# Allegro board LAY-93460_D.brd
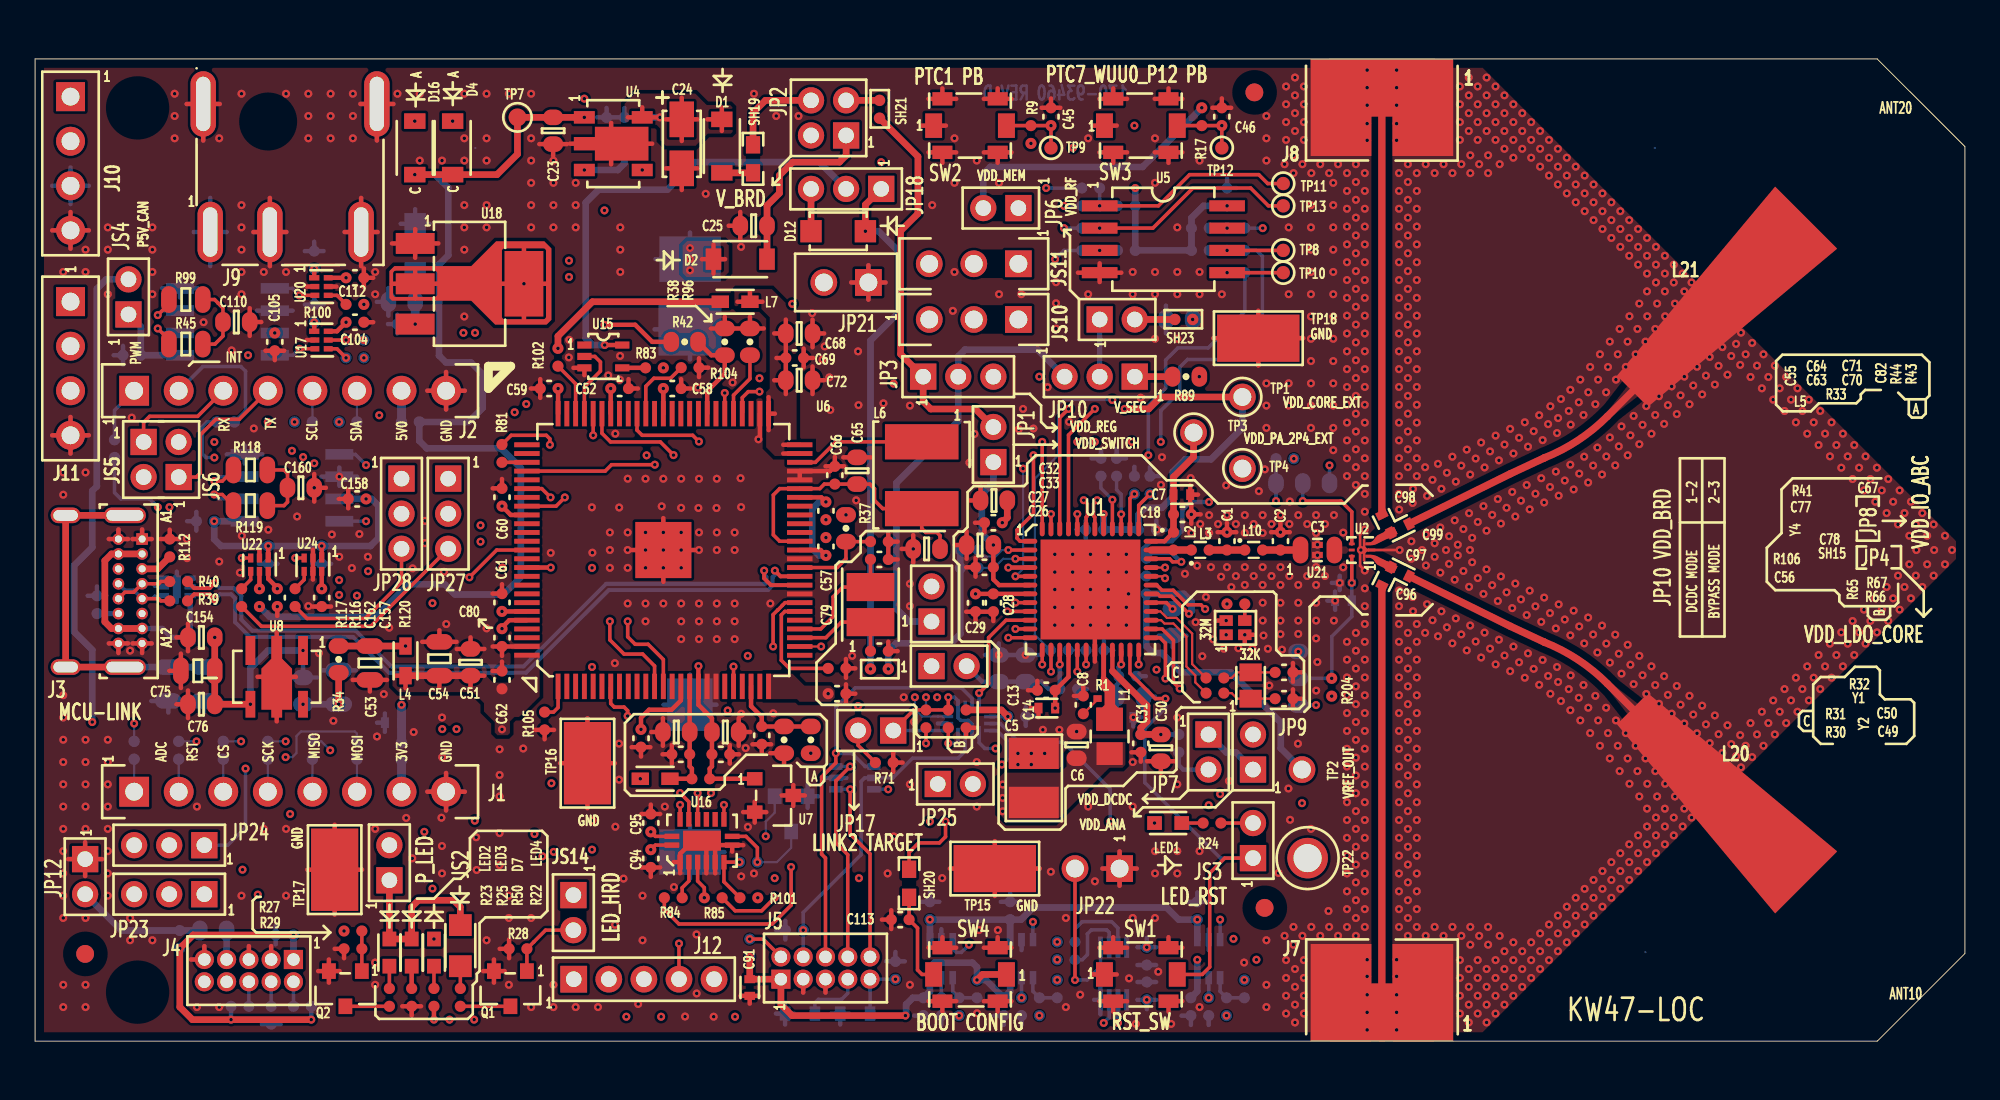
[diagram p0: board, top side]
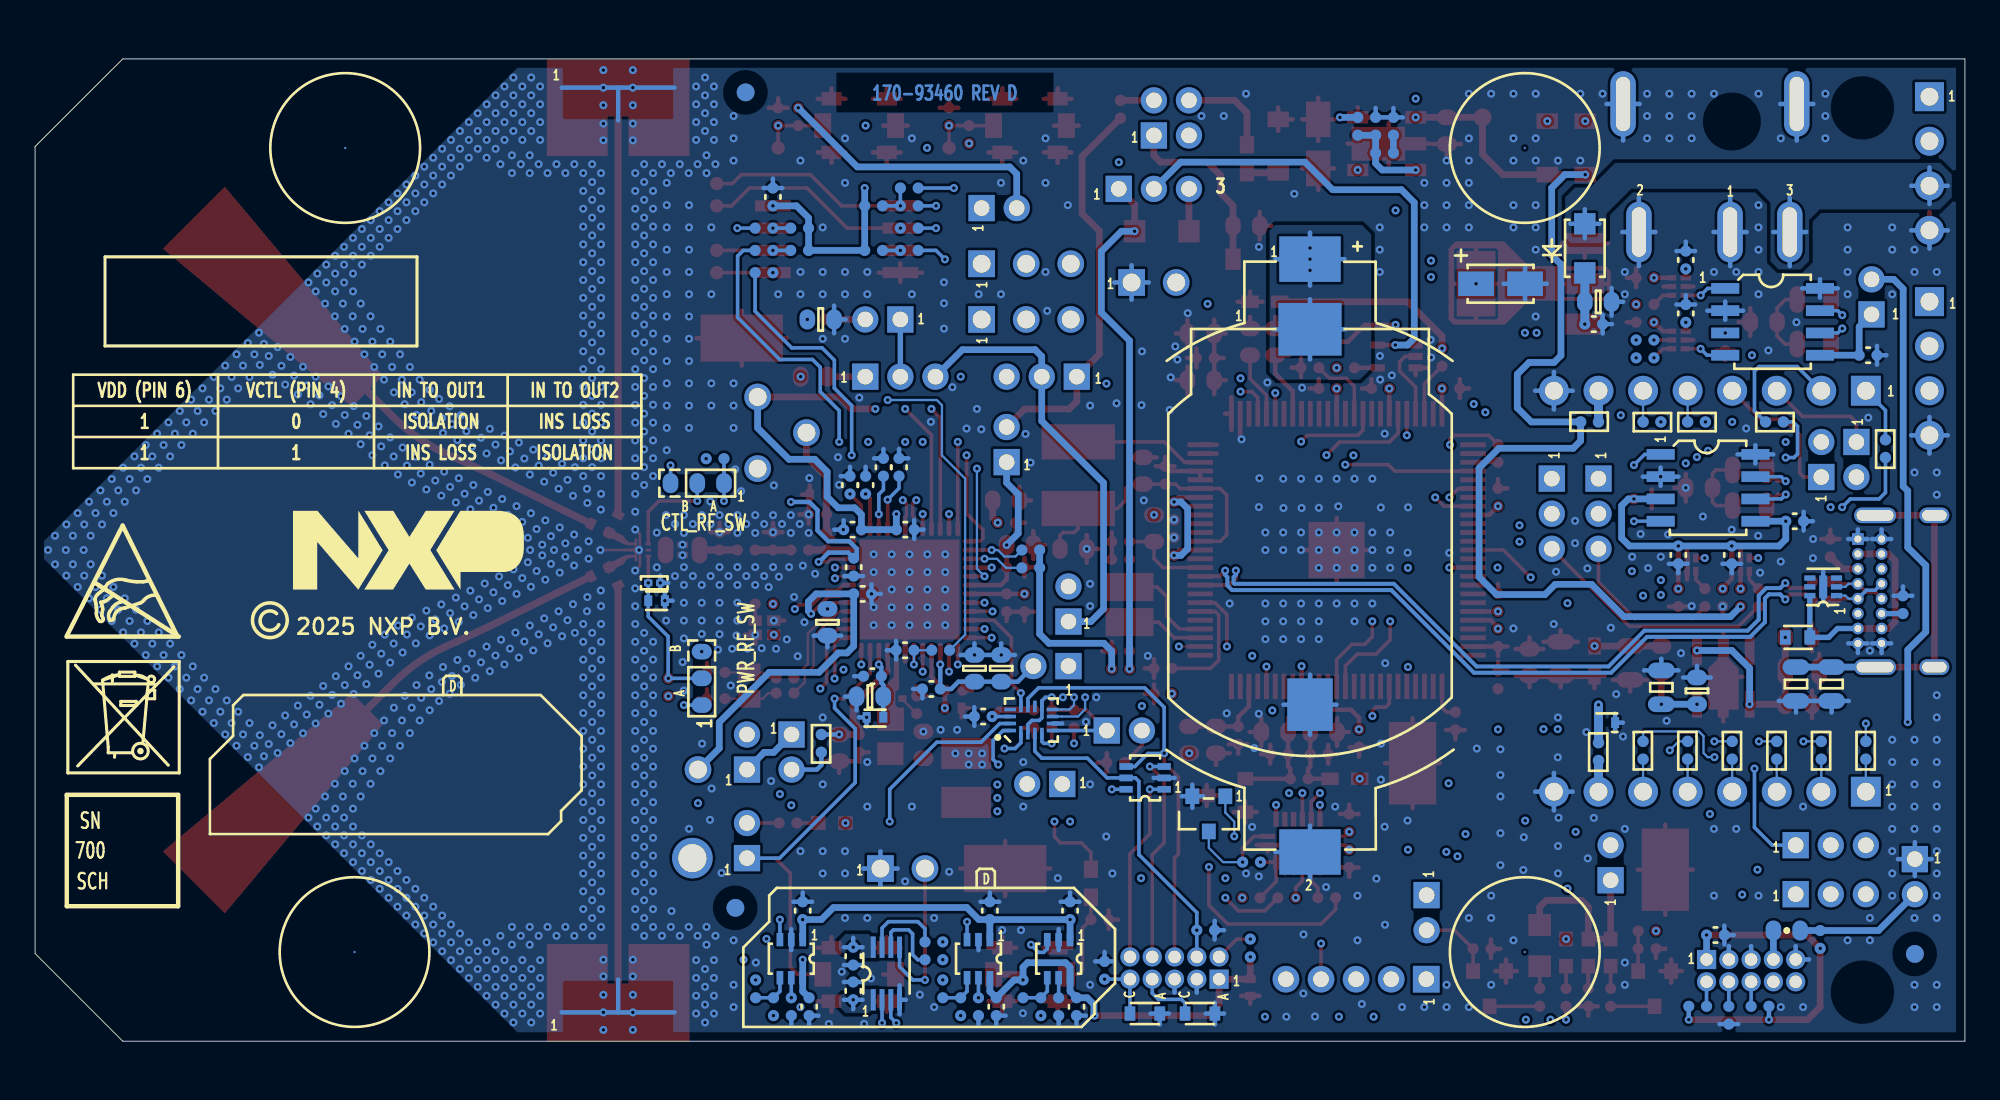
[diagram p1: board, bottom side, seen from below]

Outline 110 x 56 mm; copper layers: TOP, L2_GND_1, L3_INT_1, L4_INT_2, L5_GND_2, BOTTOM. Coordinates in mm from the lower left corner of the outline.
Outline path: 0,56 0,0 105,0 110,5 110,51 105,56 0,56

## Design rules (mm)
constraint set DEFAULT: min track width 0.203
net group CAN2_H&L_DP_100_OHM: nets CAN_HI_2 CAN_LO_2
net group CAN2_RX&TX_DP_100_OHM: nets CAN_RX_2 CAN_TX_2
net group CAN2_XTND_RX&TX_DP_100_OHM: nets UART1_RX/CAN1_RX UART1_TX/CAN1_TX
net group CAN_H&L_DP_100_OHM: nets CAN_HI_1 CAN_LO_1
net group CAN_RX&TX_DP_100_OHM: nets CAN_RX_1 CAN_TX_1
net group CAN_XTND_RX&TX_DP_100_OHM: nets CAN0_RX CAN0_TX
net group UART0_DP_100_OHM: nets UART0_RX UART0_TX
net group USB_DP_90_OHM: nets FL_USB1_DM FL_USB1_DP
net group XTAL_RF_DP: nets EXTAL_RF XTAL_RF

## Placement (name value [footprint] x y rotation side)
ANT10  F_Antenna  [ANT_KW47_B]  94.37 15.63 225 top
ANT20  F_Antenna  [ANT_KW47_B]  94.37 40.37 315 top
BMP1  BUMPER_312MIL  [BUMPER_RD_312MIL]  92.32 50.92 180 bottom
BMP2  BUMPER_312MIL  [BUMPER_RD_312MIL]  91.79 5.08 180 bottom
BMP3  BUMPER_312MIL  [BUMPER_RD_312MIL]  25.09 5.08 180 bottom
BMP4  BUMPER_312MIL  [BUMPER_RD_312MIL]  25.09 50.92 180 bottom
BT1  SMTU2450N-LF  [CON2_BH_CR2430]  37.33 27.68 270 bottom
BT2  S8421-45R  [BATTERY_HOLDER_2032_SM]  37.33 27.68 0 bottom
C1  3.3PF  [CC0402_25]  67.94 28.51 90 top
C2  1PF  [CC0402_25]  70.99 28.51 90 top
C3  15PF  [CC0805_OV]  73.09 28 0 top
C5  1uF  [CC1210]  56.93 15.01 90 top
C6  0.01uf  [CC0603_OV]  59.37 16.89 90 top
C7  1uF  [CC0402_TOL0P2]  65.36 31.16 0 top
C8  47pF  [CC0402_25]  59.75 19.18 90 top
C13  4.7uF  [CC0402_TOL0P2]  57.67 18.99 180 top
C14  0.1UF  [CC0402_25]  57.64 20.01 180 top
C15  0.22uF  [CC0402_25]  62.83 25.5 180 bottom
C16  0.1UF  [CC0402_25]  60.4 29.16 180 bottom
C17  0.1UF  [CC0402_25]  63.41 29.16 0 bottom
C18  12pF  [CC0402_25]  65.4 30.03 0 top
C19  0.01uF  [CC0201]  74.71 26.13 180 bottom
C20  1uF  [CC0402_TOL0P2]  74.58 25.11 180 bottom
C21  3pF  [CC0402_25]  63.55 31.7 90 bottom
C22  3pF  [CC0402_25]  62.66 31.7 90 bottom
C23  10uF  [CC0603_OV]  29.53 51.9 270 top
C24  10UF  [CC3216]  36.86 51.16 270 top
C25  10uF  [CC0603_OV]  40.96 46.49 180 top
C26  0.1UF  [CC0402_25]  54.11 27.02 180 top
C27  4.7uF  [CC0603_OV]  53.86 28.29 180 top
C28  0.1UF  [CC0402_25]  54.62 24.99 270 top
C29  0.1UF  [CC0402_25]  53.61 24.99 270 top
C30  10uF  [CC0603_OV]  64.17 16.72 270 top
C31  0.1UF  [CC0402_25]  63.03 16.98 270 top
C32  4.7uF  [CC0603_OV]  54.65 30.83 180 top
C33  0.1UF  [CC0402_25]  54.62 29.56 180 top
C34  4.7uF  [CC0603_OV]  64.84 23.88 270 bottom
C35  0.1UF  [CC0402_25]  58.91 20.08 0 bottom
C36  1uF  [CC0603_OV]  56.45 21.26 90 bottom
C37  10uF  [CC0603_OV]  54.93 21.26 90 bottom
C38  4.7uF  [CC0402_TOL0P2]  62.13 18.46 0 bottom
C39  1.5uF  [CC0603_OV]  62.41 19.65 0 bottom
C40  12pF  [CC0402_25]  63.34 27.02 270 bottom
C41  10uF  [CC0603_OV]  65.22 41.14 180 bottom
C42  10uF  [CC0402_TOL0P2]  20.41 18.16 180 bottom
C43  1000pF  [CC0402_25]  60.41 22.29 0 bottom
C44  0.1UF  [CC0402_25]  67.94 48.13 90 bottom
C45  1000pF  [CC0402_25]  57.91 52.7 90 top
C46  1000pF  [CC0402_25]  67.64 52.7 90 top
C49  12pF  [CC0402_25]  71.19 19.52 0 top
C50  12pF  [CC0402_25]  71.19 21.03 0 top
C51  4.7uF  [CC0603_OV]  24.82 21.6 90 top
C52  0.1UF  [CC0402_25]  33.32 37.21 0 top
C53  10uF  [CC0805_OV]  19.08 21.56 270 top
C54  10uF  [CC0805_OV]  23.04 21.8 90 top
C55  0.1UF  [CC0402_25]  34.54 17.27 270 top
C56  0.1UF  [CC0402_25]  45.71 19.81 0 top
C57  0.1UF  [CC0402_25]  45.08 30.23 270 top
C58  0.1UF  [CC0402_25]  36.32 37.21 0 top
C59  0.01UF  [CC0402_25]  29.3 37.21 180 top
C60  0.01UF  [CC0402_25]  26.61 31.01 90 top
C61  0.01UF  [CC0402_25]  26.61 25.01 90 top
C62  0.01UF  [CC0402_25]  26.61 20.59 90 top
C63  0.1UF  [CC0402_25]  36.8 16.36 180 top
C64  47pF  [CC0603_OV]  36.55 17.63 180 top
C65  47pF  [CC0603_OV]  46.86 32.52 90 top
C66  0.1UF  [CC0402_25]  45.59 32.27 90 top
C67  22uF  [CC0603_OV]  50.82 28.06 180 top
C68  22uF  [CC0603_OV]  43.55 40.35 0 top
C69  0.1UF  [CC0402_25]  43.3 38.95 0 top
C70  0.1UF  [CC0402_25]  39.09 16.36 0 top
C71  0.01uf  [CC0603_OV]  39.34 17.63 0 top
C72  47pF  [CC0603_OV]  43.55 37.68 0 top
C73  0.022UF  [CC0603_OV]  15.27 19.97 90 bottom
C74  10uF  [CC0805_OV]  17.3 20.17 90 bottom
C75  10uF  [CC0805_OV]  9.27 21.11 180 top
C76  0.022UF  [CC0603_OV]  9.48 19.21 180 top
C77  12pF  [CC0402_25]  48.13 27.46 0 top
C78  12pF  [CC0402_25]  48.13 22.24 0 top
C79  0.1UF  [CC0402_25]  45.08 28.2 90 top
C80  0.1UF  [CC0402_25]  26.61 23.01 270 top
C82  0.1UF  [CC0402_25]  41.42 17.43 270 top
C83  0.1UF  [CC0402_25]  14.22 6.05 180 bottom
C84  0.1UF  [CC0402_25]  55.96 18.51 0 bottom
C85  0.1UF  [CC0402_25]  63.37 4.85 270 bottom
C86  0.1UF  [CC0402_25]  63.37 2.87 90 bottom
C87  0.1UF  [CC0402_25]  51.01 7.44 90 bottom
C88  0.1UF  [CC0402_25]  50.64 1.97 270 bottom
C89  0.1UF  [CC0402_25]  66.25 7.44 90 bottom
C90  0.1UF  [CC0402_25]  65.88 1.97 270 bottom
C91  10uF  [CC0402_TOL0P2]  40.73 3.06 270 top
C92  0.1UF  [CC0402_25]  55.58 7.44 90 bottom
C93  0.1UF  [CC0402_25]  55.21 1.97 270 bottom
C94  0.1UF  [CC0402_25]  35.1 10.41 270 top
C95  0.1UF  [CC0402_25]  35.1 12.44 90 top
C96  15pF  [CC0402_ALT_NSP]  77.02 26.5 243.7 top
C97  15pF  [CC0402_ALT_NSP]  77.79 26.76 333.7 top
C98  15pF  [CC0402_ALT_NSP]  77.02 29.5 116.3 top
C99  15pF  [CC0402_ALT_NSP]  77.79 29.24 26.3 top
C103  0.1UF  [CC0402_25]  15.91 41.49 90 bottom
C104  0.1UF  [CC0402_25]  18.23 40.99 0 top
C105  0.1UF  [CC0402_25]  13.66 39.87 270 top
C106  0.1UF  [CC0402_25]  5.52 39.11 180 bottom
C107  10UF  [CC0603_OV]  20.9 42.15 180 bottom
C108  0.1UF  [CC0402_25]  21.16 40.88 180 bottom
C109  10UF  [CC3216]  26.47 43.18 180 bottom
C110  4700PF  [CC0603_OV]  11.47 41 180 top
C111  0.1UF  [CC0402_25]  15.91 44.54 90 bottom
C112  0.1UF  [CC0402_25]  18.23 43.52 0 top
C113  1000pF  [CC0402_25]  49.31 6.93 180 top
C154  4.7uF  [CC0603_OV]  9.48 23.02 180 top
C155  0.01UF  [CC0805_OV]  7.6 20.36 90 bottom
C156  0.1UF  [CC0402_25]  13.29 27.72 270 bottom
C157  0.1UF  [CC0402_25]  16.34 25.29 270 top
C158  0.1UF  [CC0402_25]  18.36 30.91 180 top
C159  0.1UF  [CC0402_25]  9.7 29.64 180 bottom
C160  4700PF  [CC0603_OV]  15.15 31.55 180 top
C161  0.1UF  [CC0402_25]  16.34 27.72 270 bottom
C162  0.1UF  [CC0402_25]  13.81 25.29 270 top
C163  3pF  [CC0402_25]  61.64 32.72 90 bottom
C164  3pF  [CC0402_25]  60.76 32.72 90 bottom
C165  0.1uF  [CC0402_25]  62.27 20.81 0 bottom
D1  RB160M-30  [PMDU_SOD123]  39.15 51.03 90 top
D2  RB160M-30  [PMDU_SOD123]  40.19 44.58 180 top
D4  RB160M-30  [PMDU_SOD123]  23.8 50.93 90 top
D7  RED  [LED_0603]  22.74 5.05 90 top
D8  PNS40010AERX  [SOD123W]  21.66 45.2 90 bottom
D12  PMEG1020EH  [SOD123LF]  45.78 46.17 0 top
D13  PESD3V3S1UB  [SOD523]  43.6 1.57 180 bottom
D14  PESD3V3S1UB  [SOD523]  46.74 1.57 180 bottom
D15  PESD3V3L5UY  [SOT-363_0P65_SMT]  46.73 15.01 0 bottom
D16  RB160M-30  [PMDU_SOD123]  21.64 50.93 90 top
J1  CON_1X8  [CON_1X8_SKT_2P54_TH]  5.65 14.22 90 top
J2  CON_1X8  [CON_1X8_SKT_2P54_TH]  5.65 37.08 90 top
J3  USB_TYPE_C  [CON16_USB_TYPE-C_RA_TH]  6.1 28.63 270 top
J4  HDR 2X5  [CON2X5_50_TH_A]  14.73 4.66 180 top
J5  HDR 2X5  [CON2X5_50_TH_A]  42.51 3.53 0 top
J7  CON SMA EDGE  [CONN_SMA_EDGE_MOUNT_A_KW47]  76.77 2.86 270 top
J8  CON SMA EDGE  [CONN_SMA_EDGE_MOUNT_A_KW47]  76.77 53.14 90 top
J9  CON PWR 3  [CON3_PWR_JACK_TH_PJ051A]  9.98 46.13 270 top
J10  HDR 1X4 RA  [CON_HDR_4M_100_TH_RA]  2.02 53.85 270 top
J11  HDR 1X4 RA  [CON_HDR_4M_100_TH_RA]  2.02 42.16 270 top
J12  TMM-105-01-G-S  [HDR105_5M_79_TH]  30.7 3.53 90 top
JP1  MTMM-102-06-G-S-236  [HDR102_TMM]  54.62 33.01 270 top
JP2  HDR 2X2  [HDR202_TMM]  46.23 51.64 90 top
JP3  HDR_1X3  [HDR103_78MIL]  50.62 37.88 180 top
JP4  MTMM-102-06-G-S-236  [HDR102_TMM]  51.1 21.38 180 top
JP6  MTMM-102-06-G-S-236  [HDR102_TMM]  60.68 41.14 180 top
JP7  MTMM-102-06-G-S-236  [HDR102_TMM]  66.88 17.48 90 top
JP8  MTMM-102-06-G-S-236  [HDR102_TMM]  51.1 23.92 270 top
JP9  MTMM-102-06-G-S-236  [HDR102_TMM]  69.42 15.48 270 top
JP10  HDR_1X3  [HDR103_78MIL]  62.68 37.88 0 top
JP12  MTMM-102-06-G-S-236  [HDR102_TMM]  2.85 10.38 90 top
JP17  MTMM-102-06-G-S-236  [HDR102_TMM]  48.91 17.71 0 top
JP18  HDR_1X3  [HDR103_78MIL]  48.23 48.59 0 top
JP21  HDR 1X2  [HDR102_338H]  47.5 43.25 270 top
JP22  HDR 1X2  [HDR102_338H]  61.82 9.84 270 top
JP23  HDR_1X3  [HDR103_78MIL]  9.65 8.38 0 top
JP24  HDR_1X3  [HDR103_78MIL]  9.65 11.17 0 top
JP25  MTMM-102-06-G-S-236  [HDR102_TMM]  51.45 14.66 180 top
JP27  HDR_1X3  [HDR103_78MIL]  23.55 32.07 90 top
JP28  HDR_1X3  [HDR103_78MIL]  20.89 32.07 90 top
JS1  HDR 1X2  [SH_HDR102_2MM_BOTTOM]  56.05 47.49 0 top
JS2  HDR 1X2  [SH_HDR102_2MM_BOTTOM]  20.2 9.17 270 top
JS3  HDR 1X2  [SH_HDR102_2MM_BOTTOM]  69.42 10.44 270 top
JS4  HDR 1X2  [SH_HDR102_2MM_BOTTOM]  5.32 41.43 270 top
JS5  HDR 1X2  [SH_HDR102_TMM_BOTTOM]  6.19 34.16 90 top
JS6  HDR 1X2  [SH_HDR102_TMM_BOTTOM]  8.19 32.16 270 top
JS10  HDR 1x3 TH  [HDR103_SHORT1_2]  56.05 41.14 270 top
JS11  HDR 1x3 TH  [HDR103_SHORT1_2]  56.05 44.32 270 top
JS14  HDR 1X2  [SH_HDR102_2MM_BOTTOM]  30.68 8.33 90 top
L1  1uH  [IND_0805]  61.25 17.37 270 top
L2  15nH  [IND_0402_POL]  64.89 28.51 270 top
L3  1.3nH  [IND_0402_POL]  66.41 28 0 top
L4  600OHM  [IND_1P8X1MM_SM]  21.11 21.68 270 top
L5  600OHM  [IND_1P8X1MM_SM]  35.34 14.96 0 top
L6  4.7uH  [IND_5P2X5P2]  50.54 32.26 270 top
L7  600OHM  [IND_1P8X1MM_SM]  39.9 42.15 0 top
L8  330 OHM  [IND_1608]  9.54 23.02 0 bottom
L10  1.2nH  [IND_0402_POL]  69.46 28 0 top
L20  4.3nH  [IND_0402]  95.86 14.14 315 top
L21  4.3nH  [IND_0402]  95.86 41.86 45 top
LED1  SML-D14U2WT86C  [LED_0603]  64.58 12.44 0 top
LED2  LED_GREEN  [LED_0603]  20.2 5.05 270 top
LED3  LED_GREEN  [LED_0603]  21.47 5.05 270 top
LED4  BLUE  [LED2_2P34_2P1X1P25]  24.24 5.45 90 top
NOREF  -  []  60.95 3.8 0 top
NOREF#2  -  []  69.91 19.23 0 top
NOREF#3  -  []  44.96 43.25 0 top
NOREF#4  -  []  61.45 50.67 0 top
NOREF#5  -  []  0 56 0 top
NOREF#6  -  []  60.88 50.55 0 top
NOREF#7  -  []  51.22 52.2 0 top
NOREF#8  -  []  51.22 3.8 0 top
NOREF#9  -  []  53.14 34.86 90 top
NOREF#10  -  []  67.04 42.97 90 top
NOREF#11  -  []  56.81 21 90 top
NOREF#12  -  []  59.75 8.49 90 top
NOREF#13  -  []  61.45 2.28 0 top
NOREF#14  -  []  32.83 13.5 90 top
NOREF#15  -  []  43.5 41.79 90 top
NOREF#16  -  []  74.14 27.33 90 top
NOREF#17  -  []  6.1 27.78 90 top
NOREF#18  -  []  -386.85 -298.83 0 top
NOREF#19  -  []  63.28 8.38 90 top
NOREF#20  -  []  39.06 42.15 0 top
NOREF#21  -  []  72.01 19.23 90 top
NOREF#22  -  []  35.31 35.77 0 top
NOREF#23  -  []  56.66 22.25 0 top
NOREF#24  -  []  39 42.65 90 top
NOREF#25  -  []  76.38 24.76 90 top
NOREF#26  -  []  37.33 19.18 90 top
NOREF#27  -  []  60.68 43.81 0 top
NOREF#28  -  []  58.27 19.34 0 top
NOREF#29  -  []  61.59 42.96 0 top
NOREF#30  -  []  35.81 28 90 top
NOREF#31  -  []  21.11 20.84 90 top
NOREF#32  -  []  41.58 3.66 90 top
NOREF#33  -  [unnamed#2]  70.08 7.6 180 top
NOREF#34  -  []  64.89 31.16 0 top
NOREF#35  -  []  30.14 13.5 0 top
NOREF#36  -  []  40.38 3.66 0 top
NOREF#37  -  []  106.01 44.71 0 top
NOREF#38  -  []  64.6 2.28 90 top
NOREF#39  -  []  13.77 20.77 0 top
NOREF#40  -  []  -2.66 21.08 90 top
NOREF#41  -  []  67.94 43.81 90 top
NOREF#42  -  []  34.44 14.46 90 top
NOREF#43  -  []  57.19 18.99 0 top
NOREF#44  -  []  51.72 2.28 90 top
NOREF#45  -  []  1.74 21.33 90 top
NOREF#46  -  []  74.98 29.65 0 top
NOREF#47  -  []  48.38 2.39 90 top
NOREF#48  -  []  42.51 3.53 0 top
NOREF#49  -  []  59.91 29.21 0 top
NOREF#50  -  []  63.28 13.84 0 top
NOREF#51  -  []  37.2 42.65 0 top
NOREF#52  -  []  55.44 50.55 90 top
NOREF#53  -  []  -2.04 -74.68 0 top
NOREF#54  -  [unnamed#2]  69.5 54.09 180 top
NOREF#55  -  []  47.59 3.53 90 top
NOREF#56  -  []  43.5 41.79 0 top
NOREF#57  -  []  56.69 25.5 90 top
NOREF#58  -  []  67.89 23.17 0 top
NOREF#59  -  []  67.04 42.97 90 top
NOREF#60  -  []  2.85 8.38 0 top
NOREF#61  -  []  54.87 50.67 90 top
NOREF#62  -  []  1.74 21.33 0 top
NOREF#63  -  []  22.16 -1.3 90 top
NOREF#64  -  []  72.04 27.33 0 top
NOREF#65  -  []  9.65 3.39 90 top
NOREF#66  -  []  -2.66 21.08 0 top
NOREF#67  -  []  12.27 19.21 90 top
NOREF#68  -  []  60.88 2.15 0 top
NOREF#69  -  []  43.59 32.5 90 top
NOREF#70  -  []  36.76 12.65 0 top
NOREF#71  -  [unnamed#2]  5.84 2.79 0 top
NOREF#72  -  []  47.94 34.86 0 top
NOREF#73  -  []  51.14 -1.15 90 top
NOREF#74  -  []  42.81 21 0 top
NOREF#75  -  []  61.59 42.96 0 top
NOREF#76  -  []  67.94 43.81 90 top
NOREF#77  -  []  39.26 10.21 90 top
NOREF#78  -  []  60.16 25.75 0 top
NOREF#79  -  []  46.84 -1.15 0 top
NOREF#80  -  []  39.81 10.13 0 top
NOREF#81  -  []  64.6 50.67 90 top
NOREF#82  -  []  75.05 27.65 90 top
NOREF#83  -  []  59.47 19.34 90 top
NOREF#84  -  []  22.61 48.5 0 top
NOREF#85  -  []  34.5 14.96 0 top
NOREF#86  -  []  51.14 50.55 0 top
NOREF#87  -  []  75.18 24.76 0 top
NOREF#88  -  []  13.46 4.66 0 top
NOREF#89  -  []  51.72 5.33 0 top
NOREF#90  -  []  65.18 50.55 90 top
NOREF#91  -  []  39.73 11.18 90 top
NOREF#92  -  []  42.41 10.13 90 top
NOREF#93  -  []  63.66 22.25 90 top
NOREF#94  -  []  73.09 27.72 90 top
NOREF#95  -  []  74.1 25.11 0 top
NOREF#96  -  []  20.67 22.07 90 top
NOREF#97  -  []  41.73 2.39 0 top
NOREF#98  -  []  61.65 18.46 0 top
NOREF#99  -  []  67.57 22.92 0 top
NOREF#100  -  []  67.89 23.17 90 top
NOREF#101  -  []  29.43 19.67 0 top
NOREF#102  -  []  61.53 18.81 0 top
NOREF#103  -  []  74.77 38.73 90 top
NOREF#104  -  []  30.73 40.42 0 top
NOREF#105  -  []  64.76 30.81 0 top
NOREF#106  -  []  18.42 12.13 0 top
NOREF#107  -  []  51.72 50.67 0 top
NOREF#108  -  []  60.95 52.2 0 top
NOREF#109  -  []  4.75 22.68 0 top
NOREF#110  -  []  59.91 29.21 0 top
NOREF#111  -  [unnamed#2]  5.84 53.21 0 top
NOREF#112  -  []  22.61 46.6 90 top
NOREF#113  -  []  105 0 90 top
NOREF#114  -  []  69.28 19.52 90 top
NOREF#115  -  []  21.01 17.81 0 top
NOREF#116  -  []  65.18 2.15 90 top
NOREF#117  -  []  72.07 38.73 0 top
NOREF#118  -  []  37.33 27.68 90 top
NOREF#119  -  []  -350.61 219.99 0 top
NOREF#120  -  []  16.07 22.07 0 top
NOREF#121  -  []  67.94 43.81 90 top
NOREF#122  -  []  72.41 28 0 top
NOREF#123  -  []  22.21 17.81 90 top
NOREF#124  -  []  67.57 22.92 90 top
NOREF#125  -  []  62.73 18.81 90 top
NOREF#126  -  []  21.61 22.58 0 top
NOREF#127  -  []  75.05 27.65 90 top
NOREF#128  -  [unnamed#2]  2.85 4.97 180 top
NOREF#129  -  []  40.73 2.58 90 top
NOREF#130  -  []  34.44 15.46 0 top
NOREF#131  -  []  57.05 8.49 0 top
NOREF#132  -  []  74.12 10.44 0 top
NOREF#133  -  []  15.51 -1.3 0 top
NOREF#134  -  []  36.76 12.65 0 top
NOREF#135  -  []  28.04 34 0 top
NOREF#136  -  []  19.94 18.16 0 top
NOREF#137  -  []  50.54 30.36 90 top
NOREF#138  -  []  37.33 14.94 90 top
NOREF#139  -  []  21.61 21.58 90 top
NOREF#140  -  []  60.68 43.81 0 top
NOREF#141  -  []  59.28 9.84 0 top
NOREF#142  -  []  67.94 43.81 90 top
NOREF#143  -  []  107.5 2.5 0 top
NOREF#144  -  []  74.98 28.55 90 top
NOREF#145  -  []  2.85 8.38 0 top
NOREF#146  -  []  21.11 12.13 90 top
NOREF#147  -  []  65.96 30.81 90 top
NOREF#148  -  []  2.85 8.38 0 top
NOREF#149  -  []  60.16 25.75 90 top
NOREF#150  -  []  108.14 15.29 180 bottom
NOREF#151  -  [unnamed#2]  69.5 54.09 180 bottom
NOREF#152  -  []  88.23 44.71 0 bottom
NOREF#153  -  []  108.18 23.07 180 bottom
NOREF#154  -  []  95.29 25.74 180 bottom
NOREF#155  -  []  96.62 23.97 180 bottom
NOREF#156  -  [unnamed#2]  70.08 7.6 180 bottom
NOREF#157  -  [unnamed#2]  2.85 4.97 180 bottom
Q1  BSH111BK  [SOT23_A]  27.09 2.99 180 top
Q2  BSH111BK  [SOT23_A]  17.69 2.99 180 top
Q3  BSS138P  [SOT23_A]  43.1 12.96 0 bottom
R1  22  [RC0201]  60.9 19.53 180 top
R8  100  [RC0402_25]  58.38 22.29 180 bottom
R9  10K  [RC0402_25]  56.76 51.69 90 top
R10  10K  [RC0402_25]  66.42 45.08 0 bottom
R11  10K  [RC0402_25]  62.2 47.62 180 bottom
R12  0  [RC0402_25]  68.45 45.08 180 bottom
R13  0  [RC0402_25]  60.17 46.35 0 bottom
R14  0  [RC0402_25]  68.45 43.81 180 bottom
R15  0  [RC0402_25]  60.17 45.08 0 bottom
R16  0  [RC0402_25]  60.17 47.62 0 bottom
R17  10K  [RC0402_25]  66.5 52.7 270 top
R18  0  [RC0402_25]  68.45 46.35 180 bottom
R19  10K  [RC0402_25]  62.2 45.08 180 bottom
R20  10K  [RC0402_25]  66.42 46.35 0 bottom
R21  0  [RC0402_25]  60.17 48.64 0 bottom
R22  270  [RC0402_25]  24.24 2.5 90 top
R23  510  [RC0402_25]  20.2 2.5 270 top
R24  100  [RC0402_25]  67.08 12.44 0 top
R25  510  [RC0402_25]  21.47 2.5 270 top
R27  0  [RC0402_25]  18.12 6.28 180 top
R28  10K  [RC0402_25]  27.53 5.26 0 top
R29  10K  [RC0402_25]  18.12 5.26 0 top
R30  0  [RC0402_25]  67.25 19.84 0 top
R31  0  [RC0402_25]  67.25 20.71 0 top
R32  0  [RC0402_25]  68.45 24.92 180 top
R33  1K  [RC0402_25]  37.95 14.96 0 top
R34  0  [RC0603_OV]  17.3 21.76 90 top
R37  10K  [RC0603_OV]  46.22 29.24 270 top
R38  0  [RC0603_OV]  39.31 39.87 270 top
R39  0  [RC0402_25]  8.18 25.1 0 top
R40  0  [RC0402_25]  8.18 26.2 0 top
R41  20K  [RC0402_25]  48.13 28.48 0 top
R42  0  [RC0603_OV]  37.02 39.87 180 top
R43  2.0K  [RC0603_OV]  44.22 17.18 90 top
R44  2.0K  [RC0603_OV]  42.69 17.18 270 top
R45  60.4  [RC0805_OV]  8.59 39.74 0 top
R46  100K  [RC0402_25]  11.68 1.99 0 bottom
R47  100K  [RC0402_25]  15.23 1.99 180 bottom
R48  100K  [RC0402_25]  8.25 5.8 90 bottom
R50  510  [RC0402_25]  22.74 2.5 90 top
R51  0  [RC0603_OV]  10.15 6.31 0 bottom
R53  100K  [RC0402_25]  13.46 1.48 270 bottom
R63  10  [RC0402_25]  58.77 5.66 180 bottom
R64  10  [RC0402_25]  58.77 4.64 180 bottom
R65  0  [RC0402_25]  50.78 18.37 90 top
R66  100K  [RC0402_25]  52.56 17.87 0 top
R67  100K  [RC0402_25]  52.56 18.88 0 top
R68  160K  [RC0402_25]  53.69 2.98 270 bottom
R69  100  [RC0402_25]  52.67 1.97 270 bottom
R70  2.2K  [RC0402_25]  51.66 1.97 270 bottom
R71  10  [RC0402_25]  48.4 15.88 0 top
R72  100K  [RC0402_25]  68.93 2.98 270 bottom
R73  100  [RC0402_25]  67.91 1.97 270 bottom
R74  2.2K  [RC0402_25]  66.9 1.97 270 bottom
R75  10K  [RC0402_25]  40.73 5.31 90 bottom
R76  100K  [RC0402_25]  58.26 2.98 270 bottom
R77  2.2K  [RC0402_25]  49.04 4.04 90 bottom
R78  100  [RC0402_25]  57.24 1.97 270 bottom
R79  10K  [RC0402_25]  43.27 6.33 180 bottom
R80  2.2K  [RC0402_25]  56.23 1.97 270 bottom
R81  1K  [RC0402_25]  26.61 33.51 90 top
R83  1K  [RC0402_25]  35.3 38.39 0 top
R84  100  [RC0402_25]  36.38 8.18 180 top
R85  100  [RC0402_25]  38.65 8.18 0 top
R86  10K  [RC0402_25]  40.66 10.21 0 bottom
R89  0  [RC0603_OV]  65.6 37.88 180 top
R96  0  [RC0603_OV]  40.75 39.87 90 top
R97  4.7K  [RC0402_25]  18.23 39.97 180 bottom
R98  0  [RC0402_25]  18.23 38.96 0 bottom
R99  60.4  [RC0805_OV]  8.59 42.28 180 top
R100  0  [RC0402_25]  18.23 42 0 top
R101  100K  [RC0402_25]  40.69 8.18 0 top
R102  1K  [RC0402_25]  29.8 38.99 90 top
R104  1K  [RC0402_25]  37.33 38.4 0 top
R105  1K  [RC0402_25]  29.04 18.25 270 top
R106  1K  [RC0402_25]  45.71 21.25 0 top
R112  5.1K  [RC0402_25]  7.67 28.12 90 top
R113  5.1K  [RC0402_25]  3.53 24.88 90 bottom
R114  1M  [RC0805_OV]  9.63 20.36 90 bottom
R115  100K  [RC0402_25]  71.24 33.21 180 bottom
R116  4.7K  [RC0402_25]  12.79 25.29 90 top
R117  0  [RC0402_25]  11.77 25.29 270 top
R118  60.4  [RC0805_OV]  12.27 32.56 180 top
R119  60.4  [RC0805_OV]  12.27 30.53 0 top
R120  0  [RC0402_25]  14.82 25.29 270 top
R200  39K  [RC0402_25]  34.61 52.16 270 bottom
R201  28K  [RC0402_25]  33.59 52.16 90 bottom
R202  22.6K  [RC0402_25]  33.08 50.63 180 bottom
R203  0  [RC0402_25]  32.57 52.16 90 bottom
R204  0  [RC0402_25]  73.91 20.18 90 top
R205  4.7K  [RC0402_25]  53.25 28 0 bottom
R206  4.7K  [RC0402_25]  53.25 26.98 0 bottom
SH1  0  [SH0402]  8.19 16.58 90 bottom
SH2  0  [SH0402]  5.65 16.58 90 bottom
SH3  0  [SH0402]  4.53 33.78 90 bottom
SH4  0  [SH0402]  10.73 16.58 90 bottom
SH5  0  [SH0402]  10.85 35.3 0 bottom
SH6  0  [SH0402]  13.27 16.58 90 bottom
SH8  0  [SH0402]  15.81 16.58 90 bottom
SH9  0  [SH0603-X2_PIN1TO2]  72 19.92 90 bottom
SH10  0  [SH0402]  18.35 16.58 90 bottom
SH11  0  [SH0402]  15.3 35.3 0 bottom
SH12  0  [SH0402]  20.89 16.51 90 bottom
SH13  0  [SH0402]  17.84 35.3 0 bottom
SH14  0  [SH0402]  21.39 35.3 180 bottom
SH15  0  [SH0402]  48.13 21.22 180 top
SH19  0  [SH0603]  40.92 50.3 270 top
SH20  0  [SH0603]  49.82 9 270 top
SH21  0  [SH0402]  48.13 53.13 270 top
SH22  0  [SH0402]  65.18 16.98 90 bottom
SH23  0  [SH0402]  65.47 41.14 0 top
SH24  0  [SH0603-X2_PIN1TO2]  71.5 31.81 0 bottom
SW1  TL1015AF160QG  [SW2_SPST_4X3_SM]  63.03 3.8 0 top
SW2  TL1015AF160QG  [SW2_SPST_4X3_SM]  53.29 52.2 0 top
SW3  TL1015AF160QG  [SW2_SPST_4X3_SM]  63.03 52.2 0 top
SW4  TL1015AF160QG  [SW2_SPST_4X3_SM]  53.29 3.8 180 top
TP1  TESTLOOP_LP  [TEST_LOOP]  68.81 36.72 0 top
TP2  TESTLOOP_LP  [TEST_LOOP]  72.21 15.48 0 top
TP3  TESTLOOP_LP  [TEST_LOOP]  66.03 34.69 0 top
TP4  TESTLOOP_LP  [TEST_LOOP]  68.81 32.64 0 top
TP7  -  [TPAD_040]  27.5 52.67 0 top
TP8  -  [TPAD_030]  71.14 45.08 0 top
TP9  -  [TPAD_030]  57.91 50.93 180 top
TP10  -  [TPAD_030]  71.14 43.81 0 top
TP11  -  [TPAD_030]  71.14 48.89 0 top
TP12  -  [TPAD_030]  67.64 50.93 0 top
TP13  -  [TPAD_030]  71.14 47.62 180 top
TP15  TP_2P7X4P7  [TP_2P7X4P7MM]  54.7 9.84 90 top
TP16  TP_2P7X4P7  [TP_2P7X4P7MM]  31.49 15.85 0 top
TP17  TP_2P7X4P7  [TP_2P7X4P7MM]  17.08 9.78 180 top
TP18  TP_2P7X4P7  [TP_2P7X4P7MM]  69.72 40.08 90 top
TP22  TESTLOOP_BLACK  [TP_TH_063]  72.53 10.44 0 top
U1  KW47B42ZB7AFTBT  [QFN_48_0P5_7X7_5P7EP]  60.16 25.75 0 top
U2  SKYA21038  [MLPD6_0P35_2EP]  75.53 28 180 top
U4  AP7361C  [SOT-89-5]  32.96 51.17 270 top
U5  MX25R6435FM2IL0  [SO8_W]  64.31 45.72 0 top
U6  LPC55S69JBD100  [HLQFP100_0P5_14X14]  35.81 28 90 top
U7  LM4040C30IDBZR  [SOT23-3]  42.12 14.01 270 top
U8  XC6227C331PR-G  [SOT89-5]  13.77 20.77 180 top
U9  RClamp0854P.TCT  [SLP1616P6]  8.08 25.9 90 bottom
U10  74LVC2T45DC  [SSOP8_DCU]  61.47 3.86 180 bottom
U11  NX3DV2567GU  [PQFN16_0P4_2P65X1P85]  53.21 18.31 180 bottom
U12  74LVC1T45GW,125  [SOT-363_0P65_SMT]  51.66 4.7 270 bottom
U13  74LVC1T45GW,125  [SOT-363_0P65_SMT]  66.9 4.7 270 bottom
U14  74LVC1T45GW,125  [SOT-363_0P65_SMT]  56.23 4.7 270 bottom
U15  74LVC1G07GW-Q100  [SC70-5]  32.39 39.04 270 top
U16  74AVC4TD245BQ  [DHVQFN16_0P5_3P6X2P6]  38.01 11.43 90 top
U17  74LVCH1T45  [UDFN6_1X1P5MM]  16.33 39.97 0 top
U18  NCP1117ST50T3G  [SOT223]  24.77 43.18 270 top
U19  TJA1462AT  [SO8_1P27_4X5]  10.96 41.01 180 bottom
U20  74LVCH1T45  [UDFN6_1X1P5MM]  16.33 43.02 0 top
U21  ZDEB202450T  [FILTER_4_2P1X1P35_SM]  73.09 28 0 top
U22  74LVCH1T45  [UDFN6_1X1P5MM]  12.79 27.16 270 top
U23  TJA1462AT  [SO8_1P27_4X5]  14.64 31.55 180 bottom
U24  74LVCH1T45  [UDFN6_1X1P5MM]  15.84 27.16 270 top
Y1  32MHz  [XTAL4_1P6X1P2]  68.42 23.57 0 top
Y2  32.768 kHz  [XTAL2_2X1P2_SM]  69.28 20.28 90 top
Y4  16MHz  [XTAL2_3P3X2P6]  47.62 24.89 90 top

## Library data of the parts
ANT10 ANT20 = ant_monopole
BMP1-BMP4 = Bumper
BT1 BT2 = BATTERY
C1-C3 C5-C8 C13-C18 C20-C23 C25-C46 C49-C80 C82-C99 C103-C108 C110-C113 C155-C165 = CAP_NP
C19 = CAP_NP: Tolerance: TOLERANCE; User Part Number: 150-80313
C24 C109 = CAP_POL
C154 = CAP_NP: tolerance: 20%
D1 D2 D4 D12 D16 = DIODE_SCHTKY
D7 LED1-LED4 = LED
D8 = DIODE
D13 D14 = DIODE_TVS
D15 = DIODE_ARRAY_5CH
J1 J2 = CONN_HDR_8X1
J3 = USB16_TYPEC_4SH
J4 J5 = CONN_HDR_5X2
J7 J8 = CONN_SMA_EDGE_4P
J9 = DC_POWER_JACK_SHD
J10 J11 = CONN_HDR_4X1
J12 = CONN_HDR_5X1
JP1 JP4 JP6-JP9 JP12 JP17 JP21 JP22 JP25 JS1-JS6 JS14 = CONN_HDR_2X1
JP2 = CONN_HDR_2X2
JP3 JP10 JP18 JP23 JP24 JP27 JP28 = CONN_HDR_3X1
JS10 JS11 = CONN_HDR_3X1_SHORT
L1 L4-L7 L20 L21 = INDUCTOR
L2 L3 L10 = INDP
L8 = BEAD: tolerance: 25%
Q1 Q2 = NMOS_2N7002BKW_3P
Q3 = MOSFET_N
R1 R8 R10 R12-R16 R18-R25 R27-R34 R37-R48 R50 R51 R53 R63-R81 R83-R85 R89 R96 R98-R102 R104-R106 R112-R115 R117-R120 R200-R204 = RES
R9 R11 R17 R97 R116 R205 R206 = RES: tolerance: 1%
R86 = RES: tolerance: 5%
SH1-SH6 SH8 SH10-SH15 SH19-SH23 = RES_SHORT-2
SH9 SH24 = RES_SHORT-3_1TO2: Tolerance: X; User Part Number: 470-80018
SW1-SW4 = SW_SPNO_2P_GND6P
TP1-TP4 TP7-TP13 TP22 = TESTLOOP
TP15-TP18 = TEST_POINT
U1 = KW47B41Z83AFTBT_HVQFN48
U2 = SKYA21038_6P
U4 = AP7361C_5P
U5 = MX25R6435FM2IL0
U6 = LPC55S69JB_HLQFP100
U7 = LM4040_SOT23
U8 = XC6227C_5P
U9 = RCLAMP1654P_NEW
U10 = 74LVC2T45DC_8P
U11 = NX3DV2567GU_XQFN_16P
U12-U14 U17 U20 U22 U24 = 74LVCH1T45_6P
U15 = 74AUP1G07GW
U16 = 74AVC4TD245BQ_DHVQFN16
U18 = LD1117AS18
U19 U23 = TJA1040T_3_8P
U21 = B9014_4P
Y1 = XTAL_13
Y2 Y4 = XTAL

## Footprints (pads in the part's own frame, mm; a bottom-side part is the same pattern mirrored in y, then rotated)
ANT_KW47_B
  custom 0.562x0.562 smd: 1(0,0.9)
  custom 0.25x0.25 smd: 2(0,1.9)
  custom 1.25x1.25 smd: 3(0,2.3)
BATTERY_HOLDER_2032_SM
  rect 3.607x2.997 smd: 1(0,-12.9)
  rect 2.591x2.997 smd: 2(0,8.5)
BUMPER_RD_312MIL
  round 0.127 smd: 1(0,0)
CC0201
  rect 0.47x0.381 smd: 1(-0.343,0) 2(0.343,0)
CC0402_25
  round 0.635 smd: 1(-0.508,0) 2(0.508,0)
CC0402_ALT_NSP
  rect 0.457x0.635 smd: 1(-0.575,0) 2(0.575,0)
CC0402_TOL0P2
  rect 0.457x0.61 smd: 1(-0.475,0) 2(0.475,0)
CC0603_OV
  oval 0.889x1.143 smd: 1(-0.762,0) 2(0.762,0)
CC0805_OV
  oval 0.889x1.524 smd: 1(-0.965,0) 2(0.965,0)
CC1210
  rect 1.778x2.845 smd: 1(-1.397,0) 2(1.397,0)
CC3216
  rect 2.032x1.397 smd: 1(-1.397,0) 2(1.397,0)
CON2_BH_CR2430
  rect 2.591x3.505 smd: 1(-16.9,0) 2(16.9,0)
CON2X5_50_TH_A
  rect 1.092x1.092 hole 0.711: 1(0,0)
  round 1.092 hole 0.711: 2(0,1.27) 3(1.27,0) 4(1.27,1.27) 5(2.54,0) 6(2.54,1.27) 7(3.81,0) 8(3.81,1.27) 9(5.08,0) 10(5.08,1.27)
CON3_PWR_JACK_TH_PJ051A
  round 0 hole 2.54 unplated: (-6.3,3.3)
  oval 3.454x1.448 hole 2.819x0.813: 1(0,0) 2(0,8.6) 3(0,3.4)
  oval 3.734x1.448 hole 3.099x0.813: SH1(-7.3,9.5) SH2(-7.3,-0.4)
CON16_USB_TYPE-C_RA_TH
  rect 0.66x0.66 hole 0.406: A1(0,0)
  round 0.66 hole 0.406: A4(0.85,0) A5(1.7,0) A6(2.55,0) A7(3.4,0) A8(4.25,0) A9(5.1,0) A12(5.95,0) B1(5.95,-1.35) B4(5.1,-1.35) B5(4.25,-1.35) B6(3.4,-1.35) B7(2.55,-1.35) B8(1.7,-1.35) B9(0.85,-1.35) B12(0,-1.35)
  oval 0.889x2.388 hole 0.61x2.108: SH1(-1.35,-0.98) SH2(7.3,-0.98)
  oval 0.889x1.702 hole 0.61x1.397: SH3(-1.35,-4.36) SH4(7.3,-4.36)
CON_1X8_SKT_2P54_TH
  rect 1.702x1.702 hole 1.016: 1(0,0)
  round 1.702 hole 1.016: 2(0,-2.54) 3(0,-5.08) 4(0,-7.62) 5(0,-10.16) 6(0,-12.7) 7(0,-15.24) 8(0,-17.78)
CON_HDR_4M_100_TH_RA
  rect 1.651x1.651 hole 1.016: 1(0,0)
  round 1.651 hole 1.016: 2(2.54,0) 3(5.08,0) 4(7.62,0)
CONN_SMA_EDGE_MOUNT_A_KW47
  rect 1.27x0.424 smd: 1(2.224,0)
  rect 5.537x3.463 smd: G1(0.089,2.332) G2(0.089,-2.332)
  rect 3.302x5.994 smd: G3(1.217,0)
DHVQFN16_0P5_3P6X2P6
  rect 0.305x0.838 smd: 1(-0.25,1.719) 8(-0.25,-1.719) 9(0.25,-1.719) 16(0.25,1.719)
  rect 0.838x0.305 smd: 2(-1.219,1.25) 3(-1.219,0.75) 4(-1.219,0.25) 5(-1.219,-0.25) 6(-1.219,-0.75) 7(-1.219,-1.25) 10(1.219,-1.25) 11(1.219,-0.75) 12(1.219,-0.25) 13(1.219,0.25) 14(1.219,0.75) 15(1.219,1.25)
  rect 1.143x2.159 smd: 17(0,0)
FILTER_4_2P1X1P35_SM
  rect 0.279x0.94 smd: 1(-0.688,-0.005) 3(0.688,-0.005)
  rect 0.61x0.356 smd: 2(0,-0.288) 4(0,0.288)
HDR102_338H
  rect 1.524x1.524 hole 1.016: 1(0,0)
  round 1.524 hole 1.016: 2(0,-2.54)
HDR102_TMM
  rect 1.499x1.499 hole 0.889: 1(0,0)
  round 1.499 hole 0.889: 2(-2,0)
HDR103_78MIL
  rect 1.499x1.499 hole 0.889: 1(0,0)
  round 1.499 hole 0.889: 2(-2,0) 3(-4,0)
HDR103_SHORT1_2
  rect 1.524x1.524 hole 1.016: 1(0,0)
  round 1.524 hole 1.016: 2(0,-2.54) 3(0,-5.08)
HDR105_5M_79_TH
  rect 1.524x1.524 hole 0.889: 1(0,0)
  round 1.524 hole 0.889: 2(0,-2) 3(0,-4) 4(0,-6) 5(0,-8)
HDR202_TMM
  rect 1.499x1.499 hole 0.889: 1(0,0)
  round 1.499 hole 0.889: 2(0,2) 3(2,0) 4(2,2)
HLQFP100_0P5_14X14
  rect 1.448x0.279 smd: 1(-7.775,6) 2(-7.775,5.5) 3(-7.775,5) 4(-7.775,4.5) 5(-7.775,4) 6(-7.775,3.5) 7(-7.775,3) 8(-7.775,2.5) 9(-7.775,2) 10(-7.775,1.5) 11(-7.775,1) 12(-7.775,0.5) 13(-7.775,0) 14(-7.775,-0.5) 15(-7.775,-1) 16(-7.775,-1.5) 17(-7.775,-2) 18(-7.775,-2.5) 19(-7.775,-3) 20(-7.775,-3.5) 21(-7.775,-4) 22(-7.775,-4.5) 23(-7.775,-5) 24(-7.775,-5.5) 25(-7.775,-6) 51(7.775,-6) 52(7.775,-5.5) 53(7.775,-5) 54(7.775,-4.5) 55(7.775,-4) 56(7.775,-3.5) 57(7.775,-3) 58(7.775,-2.5) 59(7.775,-2) 60(7.775,-1.5) 61(7.775,-1) 62(7.775,-0.5) 63(7.775,0) 64(7.775,0.5) 65(7.775,1) 66(7.775,1.5) 67(7.775,2) 68(7.775,2.5) 69(7.775,3) 70(7.775,3.5) 71(7.775,4) 72(7.775,4.5) 73(7.775,5) 74(7.775,5.5) 75(7.775,6)
  rect 0.279x1.448 smd: 26(-6,-7.775) 27(-5.5,-7.775) 28(-5,-7.775) 29(-4.5,-7.775) 30(-4,-7.775) 31(-3.5,-7.775) 32(-3,-7.775) 33(-2.5,-7.775) 34(-2,-7.775) 35(-1.5,-7.775) 36(-1,-7.775) 37(-0.5,-7.775) 38(0,-7.775) 39(0.5,-7.775) 40(1,-7.775) 41(1.5,-7.775) 42(2,-7.775) 43(2.5,-7.775) 44(3,-7.775) 45(3.5,-7.775) 46(4,-7.775) 47(4.5,-7.775) 48(5,-7.775) 49(5.5,-7.775) 50(6,-7.775) 76(6,7.775) 77(5.5,7.775) 78(5,7.775) 79(4.5,7.775) 80(4,7.775) 81(3.5,7.775) 82(3,7.775) 83(2.5,7.775) 84(2,7.775) 85(1.5,7.775) 86(1,7.775) 87(0.5,7.775) 88(0,7.775) 89(-0.5,7.775) 90(-1,7.775) 91(-1.5,7.775) 92(-2,7.775) 93(-2.5,7.775) 94(-3,7.775) 95(-3.5,7.775) 96(-4,7.775) 97(-4.5,7.775) 98(-5,7.775) 99(-5.5,7.775) 100(-6,7.775)
  rect 3.2x3.2 smd: 101(0,0)
IND_1P8X1MM_SM
  rect 0.991x0.711 smd: 1(-0.845,0) 2(0.845,0)
IND_5P2X5P2
  rect 2.007x4.191 smd: 1(-1.903,0) 2(1.903,0)
IND_0402
  round 0.635 smd: 1(-0.508,0) 2(0.508,0)
IND_0402_POL
  round 0.635 smd: 1(-0.508,0) 2(0.508,0)
IND_0805
  rect 1.295x1.499 smd: 1(-0.978,0) 2(0.978,0)
IND_1608
  rect 0.61x0.813 smd: 1(-0.7,0) 2(0.7,0)
LED2_2P34_2P1X1P25
  rect 1.245x1.295 smd: A(1.172,0) C(-1.172,0)
LED_0603
  rect 0.838x0.787 smd: A(-0.775,0) C(0.775,0)
MLPD6_0P35_2EP
  rect 0.33x0.152 smd: 1(-0.475,0.35) 3(-0.475,-0.35) 4(0.475,-0.35) 5(0.475,0) 6(0.475,0.35)
  custom 0.2x0.2 smd: 2(-0.475,0)
PMDU_SOD123
  rect 0.889x1.219 smd: A(1.525,0) C(-1.525,0)
PQFN16_0P4_2P65X1P85
  rect 0.203x0.762 smd: 1(-0.6,-0.724)
  rect 0.203x0.66 smd: 2(-0.2,-0.775) 3(0.2,-0.775) 4(0.6,-0.775) 9(0.6,0.775) 10(0.2,0.775) 11(-0.2,0.775) 12(-0.6,0.775)
  rect 0.66x0.203 smd: 5(1.21,-0.6) 6(1.21,-0.2) 7(1.21,0.2) 8(1.21,0.6) 13(-1.21,0.6) 14(-1.21,0.2) 15(-1.21,-0.2) 16(-1.21,-0.6)
QFN_48_0P5_7X7_5P7EP
  oval 0.864x0.279 smd: 1(-3.463,2.75) 2(-3.463,2.25) 3(-3.463,1.75) 4(-3.463,1.25) 5(-3.463,0.75) 6(-3.463,0.25) 7(-3.463,-0.25) 8(-3.463,-0.75) 9(-3.463,-1.25) 10(-3.463,-1.75) 11(-3.463,-2.25) 12(-3.463,-2.75) 25(3.463,-2.75) 26(3.463,-2.25) 27(3.463,-1.75) 28(3.463,-1.25) 29(3.463,-0.75) 30(3.463,-0.25) 31(3.463,0.25) 32(3.463,0.75) 33(3.463,1.25) 34(3.463,1.75) 35(3.463,2.25) 36(3.463,2.75)
  oval 0.279x0.864 smd: 13(-2.75,-3.463) 14(-2.25,-3.463) 15(-1.75,-3.463) 16(-1.25,-3.463) 17(-0.75,-3.463) 18(-0.25,-3.463) 19(0.25,-3.463) 20(0.75,-3.463) 21(1.25,-3.463) 22(1.75,-3.463) 23(2.25,-3.463) 24(2.75,-3.463) 37(2.75,3.463) 38(2.25,3.463) 39(1.75,3.463) 40(1.25,3.463) 41(0.75,3.463) 42(0.25,3.463) 43(-0.25,3.463) 44(-0.75,3.463) 45(-1.25,3.463) 46(-1.75,3.463) 47(-2.25,3.463) 48(-2.75,3.463)
  rect 5.69x5.69 smd: 49(0,0)
RC0201
  rect 0.47x0.381 smd: 1(-0.343,0) 2(0.343,0)
RC0402_25
  round 0.635 smd: 1(-0.508,0) 2(0.508,0)
RC0603_OV
  oval 0.889x1.143 smd: 1(-0.762,0) 2(0.762,0)
RC0805_OV
  oval 0.889x1.524 smd: 1(-0.965,0) 2(0.965,0)
SC70-5
  rect 0.406x0.813 smd: 1(-0.65,-1.079) 2(0,-1.079) 3(0.65,-1.079) 4(0.65,1.079) 5(-0.65,1.079)
SH0402
  round 0.65 smd: 1(-0.508,0) 2(0.508,0)
SH0603
  rect 0.991x0.813 smd: 1(-0.8,0) 2(0.8,0)
SH0603-X2_PIN1TO2
  oval 0.889x1.143 smd: 1(-0.762,0) 2(0.762,0) 3(2.286,0)
SH_HDR102_2MM_BOTTOM
  rect 1.499x1.499 hole 0.889: 1(0,0)
  round 1.499 hole 0.889: 2(-2,0)
SH_HDR102_TMM_BOTTOM
  rect 1.499x1.499 hole 0.889: 1(0,0)
  round 1.499 hole 0.889: 2(-2,0)
SLP1616P6
  rect 0.305x0.635 smd: 1(-0.5,-0.76) 2(0,-0.76) 3(0.5,-0.76) 4(0.5,0.76) 5(0,0.76) 6(-0.5,0.76)
  rect 1.295x0.457 smd: 7(0,0)
SO8_1P27_4X5
  rect 1.6x0.61 smd: 1(-2.7,1.905) 2(-2.7,0.635) 3(-2.7,-0.635) 4(-2.7,-1.905) 5(2.7,-1.905) 6(2.7,-0.635) 7(2.7,0.635) 8(2.7,1.905)
SO8_W
  rect 2.032x0.635 smd: 1(-3.632,1.905) 2(-3.632,0.635) 3(-3.632,-0.635) 4(-3.632,-1.905) 5(3.632,-1.905) 6(3.632,-0.635) 7(3.632,0.635) 8(3.632,1.905)
SOD123LF
  rect 1.219x1.27 smd: A(1.549,0) C(-1.549,0)
SOD123W
  rect 1.219x1.219 smd: A(1.4,0) C(-1.4,0)
SOD523
  rect 0.61x0.813 smd: A(0.85,0) C(-0.85,0)
SOT23-3
  rect 0.762x0.889 smd: 1(-0.95,-1.1) 2(0.95,-1.1) 3(0,1.1)
SOT23_A
  rect 0.787x0.889 smd: 1(-0.94,-1.003) 2(0.94,-1.003) 3(0,1.003)
SOT89-5
  rect 0.559x1.651 smd: 1(-1.5,-1.5) 3(1.5,-1.5)
  custom 0.438x0.438 smd: 2(0,0)
  rect 0.559x1.524 smd: 4(1.5,1.564) 5(-1.5,1.564)
SOT223
  rect 1.194x2.21 smd: 1(-2.3,-3.1) 2(0,-3.1) 3(2.3,-3.1)
  rect 3.734x2.21 smd: 4(0,3.1)
SOT-89-5
  rect 0.711x1.194 smd: 1(-1.5,-1.65) 3(1.5,-1.65) 4(1.5,1.65) 5(-1.5,1.65)
  custom 0.482x0.482 smd: 2(0,-0.122)
SOT-363_0P65_SMT
  rect 0.762x0.381 smd: 1(-1.085,0.65) 2(-1.085,0) 3(-1.085,-0.65) 4(1.085,-0.65) 5(1.085,0) 6(1.085,0.65)
SSOP8_DCU
  rect 0.279x1.219 smd: 1(-0.75,-1.499) 2(-0.25,-1.499) 3(0.25,-1.499) 4(0.75,-1.499) 5(0.75,1.499) 6(0.25,1.499) 7(-0.25,1.499) 8(-0.75,1.499)
SW2_SPST_4X3_SM
  rect 0.965x1.397 smd: 1(-2.075,0) 2(2.075,0)
  rect 1.143x0.762 smd: G1(-1.575,1.525) G2(-1.575,-1.525) G3(1.575,1.525) G4(1.575,-1.525)
TEST_LOOP
  round 1.524 hole 1.016: 1(0,0)
TP_2P7X4P7MM
  rect 2.692x4.699 smd: 1(0,0)
TP_TH_063
  round 2.311 hole 1.6: 1(0,0)
TPAD_030
  round 0.762 smd: 1(0,0)
TPAD_040
  round 1.016 smd: 1(0,0)
UDFN6_1X1P5MM
  rect 0.584x0.305 smd: 1(-0.418,0.5)
  rect 0.508x0.305 smd: 2(-0.38,0) 3(-0.38,-0.5) 4(0.38,-0.5) 5(0.38,0) 6(0.38,0.5)
unnamed#2
  round 1.016 smd: (0,0)
XTAL2_2X1P2_SM
  rect 1.016x1.27 smd: 1(-0.75,0) 2(0.75,0)
XTAL2_3P3X2P6
  rect 1.6x2.718 smd: 1(-1,0) 2(1,0)
XTAL4_1P6X1P2
  rect 0.762x0.61 smd: 1(-0.531,-0.405) 2(0.531,-0.405) 3(0.531,0.405) 4(-0.531,0.405)

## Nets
1V8_DCDC: C5.1 C6.1 JP10.1 L1.2 R89.2
3V3_MIKROE: J1.7 SH12.1
5V_MIKROE: J2.7 SH14.2
GND: BT1.2(-) BT2.2(-) C1.2 C2.2 C5.2 C6.2 C7.2 C8.2 C13.2 C14.2 C15.2 C16.2 C17.2 C18.2 C19.2 C20.2 C21.2 C22.2 C23.2 C24.2 C25.2 C26.2 C27.2 C28.2 C29.2 C30.2 C31.2 C32.2 C33.2 C34.2 C35.2 C36.2 C37.2 C38.2 C39.2 C40.2 C41.2 C42.2 C43.2 C44.2 C45.2 C46.2 C49.2 C50.2 C51.2 C52.2 C53.2 C54.2 C55.2 C56.2 C57.2 C58.2 C59.2 C60.2 C61.2 C62.2 C63.2 C64.2 C65.2 C66.2 C67.2 C68.2 C69.2 C70.2 C71.2 C72.2 C73.2 C74.2 C75.2 C76.2 C77.2 C78.2 C79.2 C80.2 C82.2 C83.2 C84.2 C85.2 C86.2 C87.2 C88.2 C89.2 C90.2 C91.2 C92.2 C93.2 C94.2 C95.2 C103.2 C104.2 C105.2 C106.2 C107.2 C108.2 C109.2 C110.1 C111.2 C112.2 C113.2 C154.2 C155.1 C156.2 C157.2 C158.2 C159.2 C160.1 C161.2 C162.2 C163.2 C164.2 C165.2 D13.A D14.A D15.2 J1.8 J2.8 J3.A1 J3.A12 J3.B1 J3.B12 J4.3 J4.5 J4.9 J5.3 J5.5 J7.G1 J7.G2 J7.G3(GND3) J8.G1 J8.G2 J8.G3(GND3) J9.2 J9.3 J9.SH1 J9.SH2(SHIELD2) J10.4 J11.4 JP12.1 JP21.1 JP22.1 Q1.2(SOURCE) Q2.2(SOURCE) Q3.2(SOURCE) R25.2 R28.1 R29.1 R38.1 R41.2 R44.2 R53.2 R66.2 R70.2 R71.2 R74.2 R77.2 R79.2 R80.2 R96.2 R104.2 R105.2 R106.2 R112.2 R113.2 R114.1 R201.2 R203.2 SW1.1 SW1.G1 SW1.G2 SW1.G3 SW1.G4 SW2.1 SW2.G1 SW2.G2 SW2.G3 SW2.G4 SW3.1 SW3.G1 SW3.G2 SW3.G3 SW3.G4 SW4.G1 SW4.G2 SW4.G3 SW4.G4 TP15.1 TP16.1 TP17.1 TP18.1 U1.19(VSS_DCDC) U1.49 U2.2 U4.2 U5.4 U6.18 U6.19 U6.33 U6.37 U6.46 U6.47 U6.52 U6.99 U6.101 U7.2 U7.3 U8.2(VSS) U9.7 U10.4 U11.6 U12.2 U13.2 U14.2 U15.3 U16.2 U16.5 U16.6 U16.8 U16.17 U17.2 U18.1 U19.2 U19.8 U20.2 U20.5 U21.2 U21.4 U22.2 U23.2 U23.8 U24.2 U24.5 Y1.2 Y1.4
P3V3_BATT: BT1.1 BT2.1 D2.A
P3V3_LDO: D1.C SH19.2
P5V: C23.1 D4.C D16.C R97.1 R116.1 SH14.1 TP7.1(PIN1) U4.1 U4.4
P5V_CAN: C103.1 C105.1 C106.1 C109.1 C111.1 C156.1 C158.1 C159.1 C161.1 D16.A JS4.1 U17.1 U18.2(VOUT) U18.4 U19.3 U19.5(VIO) U20.1 U22.1 U23.3 U23.5(VIO) U24.1
P12V: D8.A J9.1 J10.3 J11.3
P12V_VBAT: C107.1 C108.1 D8.C(CATHODE) U18.3
VBAT: C25.1 D2.C JP2.1
VBAT_DCDC/VBAT_PMU: C68.1 C69.1 C72.1 L7.2 U6.49 U6.50 U6.51
VBUS_USB: J3.A4 J3.A9 J3.B4(VBUS4) J3.B9 L8.1 U9.6(VBUS)
VCC_IF_LINK: C85.1 C88.1 C90.1 C91.1 C93.1 J5.1 JP18.2 R43.1 R68.1 R72.1 R75.1 R76.1 SW4.1 U10.8(VCCB) U12.6(VCCB) U13.6(VCCB) U14.6(VCCB) U15.5
VCC_TGMCU: C84.1 C94.1 D12.A JP18.1 R67.2 R86.1 R101.1 SH15.2 U11.14(VCC) U16.1 U16.7 U16.10 U16.15
VDD_ANA: C34.1 JP9.2 U1.29
VDD_CORE: C13.1 C14.1 C16.1 C17.1 TP1.1(PIN1) U1.16 U1.41
VDD_DCDC: C30.1 C31.1 LED1.A R9.1 SH22.2 U1.21
VDD_IC: JP2.2 JP2.3 R115.1 SH9.3 SH21.1
VDD_IO_ABC: C32.1 C33.1 JP8.2 U1.4
VDD_LDO_CORE: C35.1 C36.1 C37.1 JP4.2 U1.15
VDD_MEM: C44.1 JS1.1 R10.1 R11.1 R19.1 R20.1 U5.8
VDD_PA_2G4: C7.1 C18.1 L2.1 R89.1 TP3.1(PIN1) U1.36
VDD_REG: JP3.2 JP7.1 JP8.1 JP9.1 JP10.3
VDD_RF: C40.1 C41.1 SH23.2 U1.34
VDD_SWITCH: C26.1 C27.1 JP1.1 U1.6
VOUT_SYS/VDD_SYS: C38.1 C39.1 C165.1 U1.22
ADC0_A15: C43.1 R8.1 U1.18
ADC_IN: R8.2 SH2.2
AN: J1.1 SH2.1
ANT: L2.2 L3.1 U1.35
ANT_RF: C1.1 L3.2 L10.1
BOOT_CFG: C113.1 SH20.2 SW4.2(S2)
CAN0_RX: R98.2 U1.43
CAN0_TX: R100.2 U1.42
CAN1_RX: JP27.3 R117.2
CAN1_TX: JP28.3 R120.2
CAN_DIR: R97.2 R116.2 U17.5 U22.5
CAN_HI_1: J10.1 R99.2 U19.7
CAN_HI_2: J11.1 R118.2 U23.7
CAN_LO_1: J10.2 R45.1 U19.6
CAN_LO_2: J11.2 R119.1 U23.6
CAN_RX_1: U17.3 U19.4
CAN_RX_2: U22.3 U23.4
CAN_TX_1: U19.1 U20.3
CAN_TX_2: U23.1 U24.3
CS: R11.2 R16.2 R21.2 TP11.1(PIN1) U5.1
DBGIF_DETECT: R81.1 U6.78
DBGIF_ISP0_CTRL: U6.72 U15.2
DBGIF_RESET: U6.90 U14.3
DBGIF_RESET_TXEN: R80.1 U6.71 U14.5
DBGIF_TCK_SWCLK: U6.54 U10.2
DBGIF_TDI: U6.7 U10.3
DBGIF_TDO_SWO: U6.83 U12.3
DBGIF_TMS_SWDIO: U6.81 U13.3
DBGIF_TMS_SWDIO_TXEN: R74.1 U6.66 U13.5
DBGIF_VREF: C82.1 R43.2 R44.1 U6.23
DCDC_LX: L1.1 R1.1 U1.20
EXTAL32K: R31.1 U1.28
EXTAL32K_PTD5: C50.1 R31.2 Y2.2
EXTAL_32M: R32.1 Y1.3
EXTAL_RF: R32.2 U1.33
FL_USB1_DM: R39.2 U6.35
FL_USB1_DP: R40.2 U6.34
FL_USB_5V0: C75.1 C76.1 C154.1 D4.A JS4.2 L8.2 R37.1 U8.1 U8.4
GPO0: J12.1 U1.13
GPO1: J12.2 U1.14
GPO2: JP23.3 U1.17
H/RST: R18.2 R20.2 U5.7
HW_VER_1: R102.1 U6.73
HW_VER_2: R104.1 U6.65
HW_VER_3: R105.1 U6.1
HW_VER_4: R106.1 U6.31
HW_VER_6: JP21.2 Q3.1 U6.56
HW_VER_7: JP22.2 U6.27 U10.5
HW_VER_8: R96.1 U6.55
I2C1_SCL: R15.1 R206.2 SH11.1 U1.3
I2C1_SDA: JP24.3 R18.1 R21.1 R205.2 U1.2
I2C_SCL: J2.5 SH11.2
I2C_SDA: J2.6 SH13.2
IF_DETECT: D14.C J5.9 R77.1 R81.2
IF_ISPEN: D13.C J5.7 R83.2
IF_TCK_SWDCLK: D15.5 J5.4 R63.2 R79.1 U11.3
IF_TDI: D15.3 J5.8 R64.2
IF_TDO_SWO: D15.4 J5.6 R69.2 U11.11
IF_TMS_SWDIO: D15.6(K5) J5.2 R73.2 R75.2 U11.15
IF_TRGRST_SWDRST: D15.1 J5.10(B5) R78.2 U11.7
L_B4: LED4.C(CATHODE) R22.2
L_G2: LED2.C(CATHODE) R23.1
LED1_B1: JS14.2 Q1.1 R28.2
LED2_G: Q2.3 R23.2
LED2_G2: Q2.1 R27.1 R29.2
LED4_B: Q1.3 R22.1
LED_RTS: JS3.2 R24.2
LLWU/NMI_B: J2.2 SH5.2
LPSPI_PCS0: R16.1 SH4.2 U1.46
LPSPI_SCK: R12.1 SH6.2 U1.48
LPSPI_SIN: R13.1 SH8.2 U1.47
LPSPI_SOUT: R14.1 SH10.2 U1.1
MCU_LINK_3V3: C51.1 C52.1 C54.1 C55.1 C56.1 C57.1 C58.1 C59.1 C60.1 C61.1 C62.1 C79.1 C80.1 L4.2 U6.15 U6.25 U6.38 U6.44 U6.63 U6.69 U6.75 U6.84 U6.95 U6.96 U6.100
MCU_LINK_N_16MHZ: C78.1 U6.28 Y4.1
MCU_LINK_P_16MHZ: C77.1 U6.29 Y4.2
MCU_LINK_RST: J4.10(B5) U6.32
MCU_LINK_USB_CC1: J3.A5 R112.1
MCU_LINK_USB_CC2: J3.B5 R113.1
MCU_LINK_USB_DN: J3.A7 J3.B7 R39.1 U9.1
MCU_LINK_USB_DP: J3.A6 J3.B6 R40.1 U9.2
MCU_LNK_RX: U6.70 U16.13
MCU_LNK_TX: U6.79 U16.14
MCULINK_VDDA: C63.1 C64.1 L5.2 R33.1 U6.16
MLINK_3V3: C53.1 C83.1 C86.1 C87.1 C89.1 C92.1 C95.1 J4.1 L4.1 L5.1 L7.1 R34.2 R46.1 R47.1 R48.1 R50.1 R102.2 R204.1 U10.1 U12.1 U13.1 U14.1 U16.16(VCCB)
MLINK_FB: C65.1 C66.1 C67.1 L6.2 U6.39 U6.45
MLINK_LX: L6.1 U6.48
P_LED: JS2.1 LED2.A LED3.A LED4.A
P_VDD_SWITCH: JP1.2 JP3.1 SH21.2
PIO0_5-ISP_EN: J4.7 R51.2
PIO0_5-ISP_EN-LED_SWD_ACT: D7.C(CATHODE) JP12.2 R48.2 R51.1 U6.88
PIO0_10-SWO: J4.6 R46.2 U6.21
PIO0_11-SWDCLK: J4.4 R53.1 U6.13
PIO0_12-SWDIO: J4.2 R47.2 U6.12
PO_LED: LED3.C(CATHODE) R25.1
PTD2/TMP1_CH0: JP23.2 SH3.1
PTD3/I2C1_SDA: JP24.2 SH13.1
PWM: J2.1 SH3.2
RESET: J1.2 SH1.1
RF_50: C2.1 C3.1 L10.2 U21.1
RF_A: C96.1 C97.1 U2.1
RF_ANT_1: ANT10.1 C97.2
RF_ANT_2: ANT20.1 C99.2
RF_B: C98.1 C99.1 U2.3
RF_GPO_4: J12.4 SH9.1 SH24.3 U1.24
RF_GPO_5: J12.5 R115.2 SH24.1 U1.25
RF_GPO_6: JP24.1 U1.26
RST_TGTMCU_B: JP25.2 JS3.1 SH1.2 SW1.2(S2) U1.23
RST_U11: JP25.1 U11.8
SCK: R10.2 R12.2 TP8.1(PIN1) U5.6
SI: R14.2 TP10.1(PIN1) U5.5
SO: R13.2 TP13.1(PIN1) U5.2
SPI_PSC0: J1.3 SH4.1
SPI_SCK: J1.4 SH6.1
SPI_SIN: J1.5 SH8.1
SPI_SOUT: J1.6 SH10.1
SW_50: C3.2 U2.5 U21.3(OUT)
SWD_CLK: R66.1 U1.9 U11.4
SWD_DIO: U1.8 U11.16
SWITCH_WAKEUP_B: TP4.1(PIN1) U1.5
SWO/BOOT_CFG: SH20.1 U1.10 U11.12
TMP1_CH0: C21.1 JP23.1 JS14.1 U1.37
TMP1_CH5: R27.2 U1.44
UART0_RX: JS5.2 JS10.3 U1.11
UART0_TX: JS6.2 JS11.3 U1.12
UART1_RX: JP27.1 JS10.1
UART1_RX/CAN1_RX: C163.1 JP27.2 U1.39
UART1_TX: JP28.1 JS11.1
UART1_TX/CAN1_TX: C164.1 JP28.2 U1.40
UART_RX: J2.3 JS5.1
UART_TX: J2.4 JS6.1
USB1_VBUS: R37.2 R41.1 U6.36
V_BRD: C42.1 C104.1 C112.1 C157.1 C162.1 JP2.4(B2) JS1.2 JS2.2 R17.1 R205.1 R206.1 SH12.2 SH15.1 SH19.1 U17.6(VCCB) U20.6(VCCB) U22.6(VCCB) U24.6(VCCB)
V_LDO_OUT: C24.1 D1.A R200.1 U4.5(OUT)
V_SEC: JP4.1 JP6.1 JP10.2
VOUT_MLINK: C73.1 C74.1 R34.1 U8.5
VOUT_SWITCH: C28.1 C29.1 JP3.3 U1.7
VREF_MCULINK: C70.1 C71.1 R33.2 R42.2 U6.17 U7.1(CATHODE)
VREF_OUT: C15.1 TP2.1(PIN1) U1.30
WP: R15.2 R19.2 U5.3(W\P/SIO2)
WUU0_P8: C22.1 C45.1 R9.2 SW2.2(S2) TP9.1(PIN1) U1.38
WUU0_P12/NMI_B: C46.1 J12.3 R17.2 SH5.1 SW3.2(S2) TP12.1(PIN1) U1.45
XTAL32K: R30.1 U1.27
XTAL32K_PTD4: C49.1 R30.2 Y2.1
XTAL_OUT: TP22.1(PIN1) U1.31
XTAL_RF: U1.32 Y1.1
N22669333: R63.1 U10.7
N22669352: R64.1 U10.6
N22669391: R65.1 U11.1
N22669418: JP17.1 R65.2 R67.1 U11.2 U11.5 U11.9
N22669601: R70.1 U12.5
N22669605: R68.2 R69.1 U12.4
N22669808: R72.2 R73.1 U13.4
N22669908: D12.C JP18.3
N22670160: R76.2 R78.1 U14.4
N22670341: R83.1 U15.4(Y)
N22888978: JP17.2 R71.1
N22954457: R84.1 U16.3
N22954468: R85.1 R101.2 U16.4
N22954480: Q3.3 R86.2 U16.9
N23559922: R38.2 R42.1 U6.58
N23802482: D7.A R50.2
N23938720: JS10.2 R84.2
N23938761: JS11.2 R85.2
N24355935: C8.1 R1.2
N24374306: JP7.2 SH22.1
N24374396: JP6.2 SH23.1
N24441947: C19.1 C20.1 R204.2 SH9.2 U2.6(VDD)
N24444926: C98.2 J8.1
N24446994: LED1.C(CATHODE) R24.1
N24467715: C155.2 J3.SH1 J3.SH2 J3.SH3 J3.SH4 R114.2
N24516334: SH24.2 U2.4
N24687861: R200.2 R201.1 R202.1 U4.3
N24687954: R202.2 R203.1
N24732897: C96.2 J7.1
N24840090: R98.1 U17.4
N24840097: C110.2 R45.2 R99.1
N24840123: R100.1 U20.4
N24840158: R117.1 U22.4
N24840165: C160.2 R118.1 R119.2
N24840191: R120.1 U24.4
N246568380: ANT10.3 L20.2
N246568441: ANT10.2 L20.1
N246568620: ANT20.3 L21.2
N246568681: ANT20.2 L21.1

Pads without a net: BMP1 1; BMP2 1; BMP3 1; BMP4 1; J3 A8 B8; J4 8; U6 2 3 4 5 6 8 9 10 11 14 20 22 24 26 30 40 41 42 43 53 57 59 60 61 62 64 67 68 74 76 77 80 82 85 86 87 89 91 92 93 94 97 98; U8 3; U9 3 4 5; U11 10 13; U15 1; U16 11 12

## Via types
v1: diameter 0.457, hole 0.203, TOP to BOTTOM, 1488 vias
v2: diameter 0.457, hole 0.206, TOP to BOTTOM, 193 vias

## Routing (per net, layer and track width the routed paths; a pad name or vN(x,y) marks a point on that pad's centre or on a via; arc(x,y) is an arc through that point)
1V8_DCDC: length 34.2
  TOP w0.381: JP10.1 R89.2
  L4_INT_2 w0.305: 61.69,28.28 61.69,22.33
  L4_INT_2 w0.381: JP10.1 64.83,35.74 64.83,30.39 64.17,29.73 62.61,29.73 61.69,28.81 61.69,28.28 ; v1(55.15,13.1) v1(55.15,13.87) v1(55.15,14.63) 57.7,14.63 61.32,18.25 61.32,21.97 61.69,22.33
3V3_MIKROE: length 1.8
  BOTTOM w0.508: J1.7 SH12.1
5V_MIKROE: length 1.8
  BOTTOM w0.508: SH14.2 J2.7
GND: length 725.1
  TOP w0.152: v1(75.79,26.83) 75.53,27.1 75.53,27.95 v2(75.57,28) 75.53,28.05 75.53,28.9 v1(75.79,29.17) ; U2.2 v1(77.78,28)
  TOP w0.254: 20.34,45.48 U18.1 ; U18.1 21.66,46.29 ; U18.1 22.99,45.48 ; U18.1 21.66,44.67 ; 67.29,23.98 v2(67.89,23.98) ; C69.2 44.34,38.95 ; C69.2 43.81,38.42 ; C69.2 43.81,39.48 ; 12.44,46.13 J9.3 ; J9.3 13.38,44.19 ; J9.3 14.32,46.13 ; J9.3 13.38,48.07 ; C54.2 24.02,22.77 ; C54.2 22.07,22.77 ; C54.2 23.04,23.43 ; 30.49,51.17 U4.2 ; U4.2 32.83,52.35 ; U4.2 32.83,49.98 ; U4.2 35.18,51.17 ; 19.08,19.93 C53.2 ; C53.2 18.1,20.6 ; C53.2 20.06,20.6 ; SW2.G3 55.65,53.72 ; SW2.G3 54.08,53.72 ; SW2.G3 54.87,54.32 ; 8.72,22.23 C154.2 ; C154.2 8.05,23.02 ; C154.2 8.72,23.81 ; JP21.1 47.5,44.23 ; JP21.1 47.5,42.27 ; JP21.1 48.48,43.25 ; JP21.1 46.52,43.25 ; 53.1,27.5 C27.2 ; C27.2 53.1,29.07 ; C27.2 52.44,28.29 ; C29.2 C28.2 54.62,23.95 ; C29.2 53.07,24.48 ; C29.2 53.61,23.95 ; 54.08,2.28 SW4.G1 ; SW4.G1 54.87,1.68 ; SW4.G1 55.65,2.28 ; 31.31,37.97 U15.3 30.69,38.39 ; U7.3 43.22,14.61 ; U7.3 43.22,13.41 ; U7.3 43.88,14.01 ; U7.3 42.56,14.01 ; 71.7,20.49 C50.2 ; C50.2 72.23,21.03 ; C50.2 71.7,21.56 ; 47.64,33.28 C65.2 46.07,33.28 ; 16.75,3.33 Q2.2 ; Q2.2 16.14,3.99 ; Q2.2 16.75,4.66 ; Q2.2 17.36,3.99 ; U16.8 40.37,11.18 ; U16.8 39.73,10.81 ; U16.8 38.76,11.18 ; 23.43,36.01 J2.8 ; J2.8 23.43,38.15 ; J2.8 24.49,37.08 ; J2.8 22.36,37.08 ; 2.85,9.41 JP12.1 ; JP12.1 3.82,10.38 ; JP12.1 2.85,11.34 ; JP12.1 1.89,10.38 ; C91.2 41.26,2.58 ; C91.2 40.21,2.58 ; C91.2 40.73,2.14 ; 60.67,50.67 SW3.G2 ; SW3.G2 61.45,50.07 ; SW3.G2 62.24,50.67 ; SW4.G3 52.5,2.28 ; SW4.G3 51.72,1.68 ; SW4.G3 50.93,2.28 ; 15.84,28.01 U24.2 U24.5 15.84,26.31 ; 42.69,15.76 R44.2 41.9,16.42 ; Q1.2 26.15,4.66 ; Q1.2 25.54,3.99 ; Q1.2 26.76,3.99 ; Q1.2 26.15,3.33 ; 65.39,5.33 SW1.G3 64.6,5.93 ; 36.29,15.82 C63.2 ; C63.2 35.76,16.36 ; C63.2 36.29,16.89 ; 44.32,36.89 C72.2 ; C72.2 44.32,38.47 ; C72.2 44.98,37.68 ; C105.2 14.2,39.36 ; C105.2 13.66,38.83 ; C105.2 13.13,39.36 ; 63.38,15.96 C30.2 ; C30.2 64.17,15.3 ; C30.2 64.96,15.96 ; 53.23,30.83 C32.2 53.89,31.61 ; 48.27,6.93 C113.2 ; C113.2 48.8,7.46 ; C113.2 48.8,6.4 ; C66.2 45.59,33.31 ; C66.2 45.31,32.5 U6.47 U6.46 ; C66.2 45.05,32.77 ; C66.2 46.12,32.77 ; 17.61,4.73 R29.1 17.08,5.26 ; v2(35.81,28) 35.81,29.82 ; v2(35.81,28) 37.63,28 ; v2(35.81,28) 33.99,28 ; v2(35.81,28) 35.81,26.18 ; R112.2 8.21,28.63 ; R112.2 7.14,28.63 ; R112.2 7.67,29.16 ; 38.26,9.57 U16.5 38.26,11.18 ; U8.2 13.77,23.31 ; U8.2 12.68,20.77 ; U8.2 14.86,20.77 ; U8.2 13.77,18.23 ; 60.67,5.33 SW1.G1 ; SW1.G1 61.45,5.93 ; SW1.G1 62.24,5.33 ; J1.8 23.43,15.29 ; J1.8 24.49,14.22 ; J1.8 22.36,14.22 ; J1.8 23.43,13.15 ; SW2.G1 52.5,53.72 ; SW2.G1 51.72,54.32 ; SW2.G1 50.93,53.72 ; J3.B1 5.3,22.68 ; J3.B1 4.75,22.13 ; J3.B1 4.2,22.68 ; C56.2 46.22,20.34 ; C56.2 46.75,19.81 ; C56.2 46.22,19.27 ; TP16.1 33.05,15.85 ; TP16.1 29.92,15.85 ; TP16.1 31.49,18.41 ; TP16.1 31.49,13.28 ; 26.61,21.97 C80.2 ; C80.2 26.08,22.5 ; C80.2 U6.99 ; SW2.G2 52.5,50.67 ; SW2.G2 50.93,50.67 ; SW2.G2 51.72,50.07 ; 26.08,21.1 C62.2 26.61,21.64 ; 35.94,49.76 C24.2 ; C24.2 36.86,48.53 ; C24.2 37.77,49.76 ; 60.26,3.8 SW1.1 61.65,3.8 ; SW4.G2 55.65,5.33 ; SW4.G2 54.08,5.33 ; SW4.G2 54.87,5.93 ; 50.06,27.28 v2(50.06,28.06) ; v2(50.06,28.06) 49.39,28.06 ; v2(50.06,28.06) 50.06,28.85 ; 65.84,30.64 C7.2 ; C7.2 65.84,31.68 ; C7.2 66.28,31.16 ; v2(60.16,23.72) 60.41,23.47 U1.19 60.41,21.64 ; 68.95,22.65 v2(68.95,23.17) 69.55,23.17 ; 26.08,25.52 C61.2 26.61,26.05 ; J3.A1 6.1,29.17 ; J3.A1 5.55,28.63 ; J3.A1 6.65,28.63 ; U5.4 60.68,44.35 ; U5.4 59.45,43.81 ; U5.4 61.91,43.81 ; U5.4 60.68,43.28 ; C82.2 41.95,16.93 ; C82.2 41.42,16.39 ; C82.2 40.89,16.93 ; 37.36,37.21 C58.2 36.83,37.74 ; C95.2 35.63,12.95 ; C95.2 35.1,13.48 ; C95.2 34.56,12.95 ; 54.7,8.28 TP15.1 ; TP15.1 52.14,9.84 ; TP15.1 54.7,11.4 ; TP15.1 57.27,9.84 ; 57.37,53.21 C45.2 ; C45.2 57.91,53.75 ; C45.2 58.44,53.21 ; R38.1 39.31,41.29 ; R38.1 R96.2 ; R38.1 38.52,40.63 ; 7.65,21.11 C75.2 ; C75.2 8.31,20.13 ; C75.2 8.31,22.09 ; JP22.1 62.79,9.84 ; JP22.1 61.82,8.86 ; JP22.1 61.82,10.82 ; JP22.1 60.84,9.84 ; SW3.G1 61.45,54.32 ; SW3.G1 60.67,53.72 ; SW3.G1 62.24,53.72 ; 34.56,9.9 C94.2 ; C94.2 35.1,9.37 ; C94.2 35.63,9.9 ; C25.2 40.2,47.28 ; C25.2 40.2,45.7 ; C25.2 39.53,46.49 ; 29.53,50.48 C23.2 ; C23.2 28.74,51.14 ; C23.2 30.32,51.14 ; 26.08,31.52 C60.2 26.61,32.05 ; J9.SH1 20.42,53.43 ; J9.SH1 18.54,53.43 ; J9.SH1 19.48,51.35 ; C71.2 40.1,18.41 ; C71.2 40.1,16.84 ; C71.2 40.77,17.63 ; R41.2 C77.2 49.17,27.46 ; R41.2 48.63,29.01 ; R41.2 49.17,28.48 ; 38.26,11.18 U16.17 37.51,11.43 36.76,10.68 U16.2 ; 38.26,11.18 38.76,11.18 ; 15.51,9.78 TP17.1 ; TP17.1 18.64,9.78 ; TP17.1 17.08,7.21 ; TP17.1 17.08,12.34 ; 27.02,4.73 R28.1 ; R28.1 26.48,5.26 ; R28.1 27.02,5.8 ; 34,16.76 C55.2 ; C55.2 34.54,16.23 ; C55.2 35.07,16.76 ; J3.B12 5.3,28.63 ; J3.B12 4.2,28.63 ; J3.B12 4.75,29.17 ; 36.4,10.21 U16.2 ; U16.2 36.76,9.57 ; C68.2 44.98,40.35 ; C68.2 44.32,41.13 ; C68.2 44.32,39.56 ; R96.2 41.53,40.63 ; R96.2 40.75,41.29 ; 38.76,9.57 U16.6 38.76,11.18 ; 53.6,17.87 R66.2 53.07,17.33 ; U20.5 17.18,43.02 ; 2.02,45.18 J10.4 ; J10.4 2.02,47.27 ; J10.4 0.98,46.23 ; J10.4 3.06,46.23 ; 71.7,18.99 C49.2 ; C49.2 71.7,20.06 ; C49.2 72.23,19.52 ; J9.2 19.52,46.13 ; J9.2 17.64,46.13 ; J9.2 18.58,48.07 ; J9.2 18.58,44.19 ; SW3.G4 65.39,50.67 ; SW3.G4 64.6,50.07 ; SW3.G4 63.82,50.67 ; C158.2 17.85,31.45 ; C158.2 17.85,30.38 ; C158.2 17.32,30.91 ; 51.92,52.2 SW2.1 50.52,52.2 ; 41.02,12.46 U7.2 ; U7.2 40.36,13.06 ; U7.2 41.68,13.06 ; U7.2 41.02,13.66 ; 57.19,18.47 C13.2 56.75,18.99 ; U6.52 41.31,34.39 v1(41.23,34.31) ; R105.2 29.58,17.75 ; R105.2 28.51,17.75 ; R105.2 29.04,17.21 ; J11.4 2.02,35.58 ; J11.4 2.02,33.5 ; J11.4 3.06,34.54 ; J11.4 0.98,34.54 ; 20.93,1.99 R25.2 ; R25.2 21.47,1.45 ; R25.2 22,1.99 ; SW4.G4 52.5,5.33 ; SW4.G4 50.93,5.33 ; SW4.G4 51.72,5.93 ; v2(15.91,31.55) 15.91,32.34 ; v2(15.91,31.55) 15.91,30.76 ; v2(15.91,31.55) 16.57,31.55 ; R106.2 46.75,21.25 ; R106.2 46.22,20.72 ; R106.2 46.22,21.79 ; 18.74,42.99 C112.2 ; C112.2 19.27,43.52 ; C112.2 18.74,44.05 ; 57.13,20.54 C14.2 56.59,20.01 ; 48.91,15.35 R71.2 ; R71.2 48.91,16.42 ; R71.2 49.45,15.88 ; 8.88,4.66 J4.9 9.65,5.42 ; SW3.G3 64.6,54.32 ; SW3.G3 63.82,53.72 ; SW3.G3 65.39,53.72 ; 35.13,17.63 C64.2 ; C64.2 35.79,16.84 ; C64.2 35.79,18.41 ; C51.2 25.61,22.36 ; C51.2 24.03,22.36 ; C51.2 24.82,23.02 ; v2(67.94,29.02) 68.47,29.02 ; v2(67.94,29.02) 67.94,29.55 ; v2(67.94,29.02) 67.4,29.02 ; 13.81,24.24 v2(13.81,24.78) ; 60.67,2.28 SW1.G2 ; SW1.G2 61.45,1.68 ; SW1.G2 62.24,2.28 ; 70.45,29.02 v2(70.99,29.02) ; v2(70.99,29.02) 71.52,29.02 ; v2(70.99,29.02) 70.99,29.55 ; 60.26,52.2 SW3.1 61.65,52.2 ; C59.2 28.79,37.74 ; C59.2 28.26,37.21 ; C59.2 28.79,36.67 ; 59.21,19.68 C8.2 59.75,20.22 ; C110.1 12.89,41 ; C110.1 12.23,41.79 ; C110.1 12.23,40.21 ; 49.17,22.24 C78.2 48.63,22.77 ; 8.64,53.43 9.58,53.43 ; 9.58,53.43 10.52,53.43 ; 9.58,53.43 9.58,51.35 ; C76.2 8.72,20 ; C76.2 8.05,19.21 ; C76.2 8.72,18.42 ; 67.11,53.21 C46.2 ; C46.2 67.64,53.75 ; C46.2 68.18,53.21 ; 15.48,39.97 U17.2 ; 63.03,15.93 C31.2 62.49,16.47 ; J3.A12 6.65,22.68 ; J3.A12 5.55,22.68 ; J3.A12 6.1,22.13 ; 69.72,38.52 TP18.1 ; TP18.1 69.72,41.64 ; TP18.1 67.16,40.08 ; TP18.1 72.29,40.08 ; 53.58,29.56 C33.2 54.11,29.02 ; 65.39,2.28 SW1.G4 64.6,1.68 ; J4.5 12.19,5.42 ; C104.2 19.27,40.99 ; R104.2 37.84,38.93 ; R104.2 38.38,38.4 ; R104.2 37.84,37.86 ; 54.08,50.67 SW2.G4 ; SW2.G4 54.87,50.07 ; SW2.G4 55.65,50.67 ; 15.48,43.02 U20.2 ; 15.8,24.78 C157.2 16.87,24.78 ; C26.2 53.61,27.55 ; C26.2 53.61,26.48 ; C26.2 53.07,27.02 ; 65.91,29.5 v2(65.91,30.03) ; v2(65.91,30.03) 65.91,30.57 ; v2(65.91,30.03) 66.44,30.03 ; 43.78,2.77 J5.3 ; 33.83,37.74 C52.2 34.36,37.21 ; 39.6,15.82 C70.2 ; C70.2 39.6,16.89 ; C70.2 40.13,16.36 ; J4.3 13.46,5.42 ; U22.2 12.79,28.01 ; 45.05,2.77 J5.5
  L2_GND_1 w0.254: 17.64,46.13 J9.2 ; J9.2 19.52,46.13 ; J9.2 18.58,48.07 ; J9.2 18.58,44.19 ; J3.B12 5.3,28.63 ; J3.B12 4.2,28.63 ; J3.B12 4.75,29.17 ; 6.1,22.13 J3.A12 ; J3.A12 5.55,22.68 ; J3.A12 6.65,22.68 ; 47.5,42.27 JP21.1 ; JP21.1 48.48,43.25 ; JP21.1 46.52,43.25 ; JP21.1 47.5,44.23 ; 5.55,28.63 J3.A1 ; J3.A1 6.65,28.63 ; J3.A1 6.1,29.17 ; 45.05,2.77 J5.5 ; J2.8 24.49,37.08 ; J2.8 23.43,36.01 ; J2.8 23.43,38.15 ; J2.8 22.36,37.08 ; JP22.1 62.79,9.84 ; JP22.1 60.84,9.84 ; JP22.1 61.82,10.82 ; JP22.1 61.82,8.86 ; 23.43,13.15 J1.8 ; J1.8 22.36,14.22 ; J1.8 24.49,14.22 ; J1.8 23.43,15.29 ; JP12.1 3.82,10.38 ; JP12.1 2.85,9.41 ; JP12.1 2.85,11.34 ; JP12.1 1.89,10.38 ; 0.98,46.23 J10.4 ; J10.4 3.06,46.23 ; J10.4 2.02,45.18 ; J10.4 2.02,47.27 ; 8.64,53.43 9.58,53.43 ; 9.58,53.43 9.58,51.35 ; 9.58,53.43 10.52,53.43 ; J11.4 3.06,34.54 ; J11.4 2.02,35.58 ; J11.4 2.02,33.5 ; J11.4 0.98,34.54 ; J9.SH1 20.42,53.43 ; J9.SH1 19.48,51.35 ; J9.SH1 18.54,53.43 ; J3.B1 5.3,22.68 ; J3.B1 4.2,22.68 ; J3.B1 4.75,22.13 ; 13.38,44.19 J9.3 ; J9.3 14.32,46.13 ; J9.3 12.44,46.13 ; J9.3 13.38,48.07 ; J4.3 13.46,5.42 ; J4.5 12.19,5.42 ; 9.65,5.42 J4.9 8.88,4.66 ; 43.78,2.77 J5.3
  L3_INT_1 w0.254: J1.8 24.49,14.22 ; J1.8 22.36,14.22 ; J1.8 23.43,15.29 ; J1.8 23.43,13.15 ; J3.B12 5.3,28.63 ; J3.B12 4.2,28.63 ; J3.B12 4.75,29.17 ; J3.A12 6.65,22.68 ; J3.A12 5.55,22.68 ; J3.A12 6.1,22.13 ; J4.5 12.19,5.42 ; 2.02,33.5 J11.4 ; J11.4 3.06,34.54 ; J11.4 2.02,35.58 ; J11.4 0.98,34.54 ; 45.05,2.77 J5.5 ; 5.55,28.63 J3.A1 ; J3.A1 6.65,28.63 ; J3.A1 6.1,29.17 ; JP22.1 62.79,9.84 ; JP22.1 61.82,8.86 ; JP22.1 60.84,9.84 ; 19.48,51.35 J9.SH1 ; J9.SH1 20.42,53.43 ; J9.SH1 18.54,53.43 ; 9.58,51.35 9.58,53.43 ; 9.58,53.43 8.64,53.43 ; 9.58,53.43 10.52,53.43 ; J9.3 14.32,46.13 ; J9.3 13.38,44.19 ; J9.3 13.38,48.07 ; J9.3 12.44,46.13 ; 18.58,44.19 J9.2 ; J9.2 19.52,46.13 ; J9.2 18.58,48.07 ; J9.2 17.64,46.13 ; 2.85,9.41 JP12.1 ; JP12.1 1.89,10.38 ; JP12.1 3.82,10.38 ; JP12.1 2.85,11.34 ; 4.2,22.68 J3.B1 ; J3.B1 5.3,22.68 ; J3.B1 4.75,22.13 ; 43.78,2.77 J5.3 ; 2.02,45.18 J10.4 ; J10.4 0.98,46.23 ; J10.4 2.02,47.27 ; J10.4 3.06,46.23 ; 8.88,4.66 J4.9 9.65,5.42 ; J4.3 13.46,5.42
  L4_INT_2 w0.254: J3.B12 4.75,29.17 ; J3.B12 4.2,28.63 ; J3.B12 5.3,28.63 ; 18.54,53.43 J9.SH1 ; J9.SH1 20.42,53.43 ; J9.SH1 19.48,51.35 ; 5.55,22.68 J3.A12 ; J3.A12 6.65,22.68 ; J3.A12 6.1,22.13 ; 4.75,22.13 J3.B1 ; J3.B1 5.3,22.68 ; J3.B1 4.2,22.68 ; J3.A1 6.65,28.63 ; J3.A1 6.1,29.17 ; J3.A1 5.55,28.63 ; J9.3 14.32,46.13 ; J9.3 13.38,44.19 ; J9.3 12.44,46.13 ; J9.3 13.38,48.07 ; 9.58,53.43 10.52,53.43 ; 9.58,53.43 8.64,53.43 ; 9.58,53.43 9.58,51.35 ; JP12.1 2.85,11.34 ; JP12.1 2.85,9.41 ; JP12.1 1.89,10.38 ; JP12.1 3.82,10.38 ; J9.2 18.58,48.07 ; J9.2 18.58,44.19 ; J9.2 19.52,46.13 ; J9.2 17.64,46.13 ; 2.02,45.18 J10.4 ; J10.4 3.06,46.23 ; J10.4 2.02,47.27 ; 0.98,34.54 J11.4 ; J11.4 2.02,35.58 ; J11.4 3.06,34.54 ; J11.4 2.02,33.5 ; 8.88,4.66 J4.9 9.65,5.42 ; JP22.1 61.82,10.82 ; JP22.1 60.84,9.84 ; JP22.1 62.79,9.84 ; JP22.1 61.82,8.86 ; J4.5 12.19,5.42
  L5_GND_2 w0.254: J2.8 24.49,37.08 ; J2.8 23.43,36.01 ; J2.8 22.36,37.08 ; J2.8 23.43,38.15 ; J10.4 2.02,47.27 ; J10.4 0.98,46.23 ; J10.4 3.06,46.23 ; J10.4 2.02,45.18 ; J3.A1 6.65,28.63 ; J3.A1 6.1,29.17 ; J3.A1 5.55,28.63 ; J9.SH1 20.42,53.43 ; J9.SH1 19.48,51.35 ; J9.SH1 18.54,53.43 ; 9.65,5.42 J4.9 8.88,4.66 ; J9.3 14.32,46.13 ; J9.3 13.38,48.07 ; J9.3 13.38,44.19 ; J9.3 12.44,46.13 ; 61.82,8.86 JP22.1 ; JP22.1 60.84,9.84 ; JP22.1 61.82,10.82 ; JP22.1 62.79,9.84 ; 23.43,13.15 J1.8 ; J1.8 24.49,14.22 ; J1.8 22.36,14.22 ; J1.8 23.43,15.29 ; J3.B12 4.75,29.17 ; J3.B12 5.3,28.63 ; J3.B12 4.2,28.63 ; 46.52,43.25 JP21.1 ; JP21.1 47.5,42.27 ; JP21.1 48.48,43.25 ; JP21.1 47.5,44.23 ; JP12.1 2.85,11.34 ; JP12.1 2.85,9.41 ; JP12.1 1.89,10.38 ; JP12.1 3.82,10.38 ; J3.B1 5.3,22.68 ; J3.B1 4.75,22.13 ; J3.B1 4.2,22.68 ; 5.55,22.68 J3.A12 ; J3.A12 6.65,22.68 ; J3.A12 6.1,22.13 ; 43.78,2.77 J5.3 ; 9.58,53.43 10.52,53.43 ; 9.58,53.43 8.64,53.43 ; 9.58,53.43 9.58,51.35 ; 17.64,46.13 J9.2 ; J9.2 18.58,44.19 ; J9.2 18.58,48.07 ; J9.2 19.52,46.13 ; J4.3 13.46,5.42 ; 2.02,33.5 J11.4 ; J11.4 0.98,34.54 ; J11.4 2.02,35.58 ; J11.4 3.06,34.54 ; 45.05,2.77 J5.5 ; J4.5 12.19,5.42
  BOTTOM w0.254: Q3.2 44.65,13.96 ; Q3.2 44.04,14.62 ; Q3.2 44.04,13.3 ; Q3.2 43.43,13.96 ; C107.2 20.14,42.94 ; C107.2 19.48,42.15 ; C107.2 20.14,41.36 ; BT1.2 39.3,10.78 ; BT1.2 37.33,9.27 ; BT1.2 37.33,12.29 ; J7.G3 76.77,3.51 ; J7.G3 73.55,1.64 ; J7.G3 79.98,1.64 ; 11.94,32.93 U23.8 ; U23.8 12.96,33.45 ; U23.8 11.94,33.97 ; U23.8 10.93,33.45 ; v2(17.34,32.18) 18.36,32.18 ; v2(17.34,32.18) 16.33,32.18 ; v2(17.34,32.18) 17.34,31.66 ; v2(17.34,32.18) 17.34,32.7 ; 2.02,33.5 J11.4 ; J11.4 3.06,34.54 ; J11.4 0.98,34.54 ; J11.4 2.02,35.58 ; J4.3 13.46,5.42 ; 13.29,26.68 C156.2 ; C156.2 13.82,27.21 ; C156.2 12.76,27.21 ; 23.84,43.18 C109.2 ; C109.2 25.07,42.26 ; C109.2 25.07,44.09 ; C109.2 26.3,43.18 ; 62.83,3.37 C86.2 63.9,3.37 ; C74.2 18.28,21.14 ; C74.2 16.33,21.14 ; C74.2 17.3,21.8 ; 62.18,33.23 C163.2 61.64,33.76 ; 13.66,41.12 U19.2 ; U19.2 12.65,41.65 ; U19.2 14.68,41.65 ; U19.2 13.66,42.17 ; J8.G3 79.98,54.36 ; J8.G3 76.77,52.49 ; J8.G3 73.55,54.36 ; J9.3 13.38,48.07 ; J9.3 14.32,46.13 ; J9.3 13.38,44.19 ; J9.3 12.44,46.13 ; 22.36,37.08 J2.8 ; J2.8 23.43,36.01 ; J2.8 24.49,37.08 ; J2.8 23.43,38.15 ; C111.2 15.91,45.58 ; C111.2 16.44,45.04 ; C111.2 15.38,45.04 ; 45.05,2.77 J5.5 ; 2.85,9.41 JP12.1 ; JP12.1 3.82,10.38 ; JP12.1 1.89,10.38 ; JP12.1 2.85,11.34 ; 73.91,26.13 v2(74.37,26.13) ; v2(74.37,26.13) 74.37,26.53 ; v2(74.37,26.13) 74.37,25.72 ; C87.2 51.01,8.48 ; C87.2 50.47,7.95 ; C87.2 51.54,7.95 ; 8.26,42.39 U19.8 ; U19.8 8.26,43.44 ; U19.8 9.28,42.92 ; U19.8 7.25,42.92 ; 62.6,17.94 v2(62.6,18.46) 63.05,18.46 ; BT2.2 38.84,19.18 ; BT2.2 37.33,17.47 ; BT2.2 35.82,19.18 ; BT2.2 37.33,20.9 ; C43.2 60.92,22.82 ; C43.2 60.92,21.75 ; C43.2 61.46,22.29 ; 65.35,1.46 C90.2 65.88,0.92 ; J4.5 12.19,5.42 ; 23.43,13.15 J1.8 ; J1.8 23.43,15.29 ; J1.8 22.36,14.22 ; J1.8 24.49,14.22 ; C89.2 66.25,8.48 ; C89.2 65.71,7.95 ; C89.2 66.78,7.95 ; J9.2 19.52,46.13 ; J9.2 18.58,44.19 ; J9.2 17.64,46.13 ; J9.2 18.58,48.07 ; JP21.1 47.5,44.23 ; JP21.1 47.5,42.27 ; JP21.1 48.48,43.25 ; JP21.1 46.52,43.25 ; v2(54.93,22.02) 54.93,22.68 ; v2(54.93,22.02) v2(56.45,22.02) ; v2(54.93,22.02) 54.14,22.02 ; D13.A 42.75,2.2 ; D13.A 42.75,0.95 ; D13.A 42.23,1.57 ; D13.A 43.27,1.57 ; 3,25.39 R113.2 ; R113.2 3.53,25.93 ; R113.2 4.06,25.39 ; 8.08,26.77 U9.7 8.08,25.04 ; R77.2 49.04,5.08 ; R77.2 49.57,4.55 ; R77.2 48.51,4.55 ; 13.18,6.05 C83.2 ; C83.2 13.71,6.59 ; C83.2 13.71,5.52 ; 54.68,1.46 C93.2 55.21,0.92 ; 9.19,29.11 C159.2 ; C159.2 9.19,30.18 ; C159.2 8.66,29.64 ; 4.2,22.68 J3.B1 ; J3.B1 4.75,22.13 ; J3.B1 5.3,22.68 ; v2(62.32,25.5) 62.32,26.03 ; v2(62.32,25.5) 62.32,24.97 ; v2(62.32,25.5) 61.79,25.5 ; 66.9,5.19 U13.2 66.9,6.38 ; 56.23,0.92 R80.2 ; 5.55,28.63 J3.A1 ; J3.A1 6.1,29.17 ; J3.A1 6.65,28.63 ; v2(56.45,22.02) 57.24,22.02 ; v2(56.45,22.02) 56.45,22.68 ; 73.66,25.11 v2(74.1,25.11) ; v2(74.1,25.11) 74.1,25.63 ; v2(74.1,25.11) 74.1,24.59 ; J3.B12 5.3,28.63 ; J3.B12 4.2,28.63 ; J3.B12 4.75,29.17 ; 9.58,51.35 9.58,53.43 ; 9.58,53.43 8.64,53.43 ; 9.58,53.43 10.52,53.43 ; C16.2 59.89,29.7 ; C16.2 59.36,29.16 ; C16.2 59.89,28.63 ; 64.84,22.46 C34.2 ; C34.2 64.05,23.12 ; C34.2 65.62,23.12 ; 60.76,33.76 C164.2 60.22,33.23 ; 19.48,51.35 J9.SH1 ; J9.SH1 20.42,53.43 ; J9.SH1 18.54,53.43 ; J10.4 3.06,46.23 ; J10.4 2.02,45.18 ; J10.4 0.98,46.23 ; 56.23,5.19 U14.2 ; 63.55,32.74 C21.2 64.08,32.21 ; 8.88,4.66 J4.9 9.65,5.42 ; 67.41,48.64 C44.2 ; C44.2 67.94,49.17 ; C44.2 68.48,48.64 ; C161.2 16.87,27.21 ; C161.2 15.8,27.21 ; C161.2 16.34,26.68 ; U10.4 60.72,3.18 ; U10.4 60.72,1.53 ; U10.4 60.37,2.36 ; 50.11,1.46 C88.2 50.64,0.92 ; 63.8,41.14 C41.2 ; C41.2 64.46,40.36 ; C41.2 64.46,41.93 ; C84.2 56.47,19.04 ; C84.2 57,18.51 ; C84.2 56.47,17.97 ; 14.48,20.73 C73.2 ; C73.2 15.27,21.39 ; C73.2 16.06,20.73 ; 12.92,0.97 R53.2 13.99,0.97 ; 61.82,8.86 JP22.1 ; JP22.1 62.79,9.84 ; JP22.1 61.82,10.82 ; JP22.1 60.84,9.84 ; 6.1,22.13 J3.A12 ; J3.A12 6.65,22.68 ; J3.A12 5.55,22.68 ; 19.94,17.64 C42.2 ; C42.2 19.94,18.68 ; C42.2 19.49,18.16 ; 55.04,7.95 C92.2 ; C92.2 55.58,8.48 ; C92.2 56.11,7.95 ; 43.78,2.77 J5.3 ; C165.2 63.31,20.81 ; 63.84,19.65 C39.2 63.18,18.86 ; 32.04,52.67 R203.2 ; R203.2 R201.2 33.59,53.2 ; R203.2 32.57,53.2 ; 15.38,42 C103.2 ; C103.2 16.44,42 ; C103.2 15.91,42.53 ; 45.05,15.01 D15.2 46.24,15.01 ; 51.46,18.11 U11.6 ; 66.9,0.92 R74.2 ; 63.87,26.52 C40.2 62.81,26.52 ; 42.77,5.79 R79.2 ; R79.2 42.23,6.33 ; R79.2 42.77,6.86 ; 62.83,4.34 C85.2 63.9,4.34 ; R114.1 10.61,19.4 ; R114.1 9.63,18.74 ; R114.1 8.65,19.4 ; 4.48,39.11 C106.2 ; C106.2 5.01,39.64 ; C106.2 5.01,38.57 ; 20.65,40.34 C108.2 ; C108.2 20.65,41.41 ; C108.2 20.12,40.88 ; 64.45,29.16 C17.2 63.91,29.7 ; 45.89,0.95 D14.A ; D14.A 45.37,1.57 ; D14.A 46.41,1.57 ; 6.62,19.4 C155.1 ; C155.1 8.58,19.4 ; C155.1 7.6,18.74 ; 51.66,5.19 U12.2 51.66,6.38 ; 59.42,19.54 C35.2 59.96,20.08 ; 51.66,0.92 R70.2 ; C22.2 62.66,32.74
  vias: v1(1.61,43.85) v1(1.61,32.42) v1(1.61,31.15) v1(1.61,19.72) v1(1.61,18.45) v1(1.61,17.18) v1(1.61,15.91) v1(1.61,14.64) v1(1.61,13.37) v1(1.61,12.1) v1(1.61,10.83) v1(1.61,9.56) v1(1.61,8.29) v1(1.61,7.02) v1(1.61,3.21) v1(1.61,1.94) v1(2.88,45.12) v1(2.88,43.85) v1(2.88,32.42) v1(2.88,17.18) v1(2.88,15.91) v1(2.88,14.64) v1(2.88,13.37) v1(2.88,12.1) v1(2.88,7.02) v1(2.88,3.21) v1(2.88,1.94) v1(4.15,46.39) v1(4.15,45.12) v1(4.15,42.58) v1(4.15,17.18) v1(4.15,15.91) v1(4.15,14.64) v1(4.15,13.37) v1(4.15,12.1) v1(4.15,10.83) v1(4.15,9.56) v1(4.15,8.29) v1(5.42,22.26) v1(5.42,7.02) v1(5.42,5.75) v1(5.51,35.55) v1(6.69,46.39) v1(6.69,45.12) v1(6.69,43.85) v1(6.69,42.58) v1(6.69,5.75) v1(7.96,54.01) v1(7.96,52.74) v1(7.96,51.47) v1(8.65,28.63) v1(8.66,27.54) v1(9.23,13.37) v1(9.23,1.94) v1(9.6,40.99) v1(10.5,51.47) v1(10.5,27.34) v1(10.5,1.94) v1(11.2,39.38) v1(11.67,26.71) v1(11.77,54.01) v1(11.77,47.66) v1(11.77,46.39) v1(11.77,45.12) v1(11.77,43.85) v1(11.77,42.58) v1(11.79,28.81) v1(11.77,8.29) v1(12.47,34.93) v1(13.04,43.85) v1(13.04,12.1) v1(13.29,29.16) v1(14.31,54.01) v1(14.31,43.85) v1(14.31,12.1) v1(14.31,8.29) v1(14.93,29.91) v1(15.58,54.01) v1(15.58,52.74) v1(15.58,51.47) v1(15.58,24.8) v1(16.18,22.12) v1(16.85,54.01) v1(16.85,52.74) v1(16.85,51.47) v1(16.92,28.89) v1(17,18.26) v1(17.34,27.61) v1(18.06,26.97) v1(18.12,54.01) v1(18.12,52.74) v1(18.12,51.47) v1(18.49,28.91) v1(18.97,27.61) v1(19.39,43.85) v1(19.39,42.58) v1(19.39,12.1) v1(19.39,4.48) v1(19.39,3.21) v1(19.49,17.37) v1(19.88,19.78) v1(20.18,23.57) v1(20.66,54.01) v1(21.15,12.73) v1(21.5,10.42) v1(21.52,26.95) v1(21.58,17.62) v1(21.93,54.01) v1(21.93,50.2) v1(22.22,29.66) v1(22.22,28.39) v1(23.2,50.2) v1(23.2,18.45) v1(23.16,12.74) v1(23.19,11.12) v1(23.2,9.56) v1(23.2,16.18) v1(23.3,26.76) v1(23.44,23.78) v1(24.47,54.01) v1(24.47,51.47) v1(24.47,50.2) v1(24.47,47.66) v1(24.47,46.39) v1(24.47,45.12) v1(24.47,41.31) v1(25.14,11.63) v1(25.17,9.76) v1(25.74,54.01) v1(25.74,51.47) v1(25.74,50.2) v1(25.74,47.66) v1(25.74,46.39) v1(25.74,23.53) v1(25.74,5.75) v1(26.48,16.64) v1(26.48,15.17) v1(26.48,13.95) v1(26.48,11.86) v1(26.48,10.04) v1(27.01,54.01) v1(27.01,8.29) v1(27.01,7.02) v1(27.01,3.21) v1(27.82,16.69) v1(28.28,54.01) v1(28.28,51.47) v1(28.28,50.2) v1(28.28,48.93) v1(28.28,47.66) v1(28.28,46.39) v1(28.28,7.02) v1(28.28,1.94) v1(29.39,27.84) v1(29.55,50.2) v1(29.55,48.93) v1(29.55,47.66) v1(29.55,46.39) v1(29.55,3.21) v1(29.55,1.94) v1(30.45,39.98) v1(30.42,38.98) v1(30.82,48.93) v1(30.82,47.66) v1(30.82,46.39) v1(30.82,1.94) v1(31.74,30.43) v1(31.76,27.85) v1(31.77,12.58) v1(32.09,1.94) v1(32.67,37.95) v1(32.76,29) v1(32.76,28) v1(32.76,26.98) v1(33.07,34.63) v1(33.05,21.55) v1(33.08,12.22) v1(33.06,6.63) v1(33.29,30.42) v1(33.29,16.96) v1(33.29,14.91) v1(33.36,46.39) v1(33.36,45.12) v1(33.36,43.85) v1(33.34,39.06) v1(33.33,37.72) v1(33.54,9.27) v1(33.78,32.06) v1(33.78,29) v1(33.78,28) v1(33.78,26.98) v1(33.78,24.95) v1(34.38,2.12) v1(34.63,8.29) v1(34.63,5.75) v1(34.79,32.06) v1(34.79,24.95) v1(34.79,23.94) v1(35.72,30.49) v1(35.81,32.06) v1(35.81,24.95) v1(35.9,13.37) v1(36.41,8.78) v1(36.83,32.06) v1(36.82,30.41) v1(36.83,24.95) v1(36.83,23.94) v1(36.83,22.92) v1(37.05,1.4) v1(37.7,6.09) v1(37.78,37.25) v1(37.71,2.72) v1(37.84,32.06) v1(37.81,30.4) v1(37.84,29) v1(37.84,28) v1(37.84,24.95) v1(37.84,23.94) v1(37.84,22.92) v1(38.23,48.31) v1(38.68,1.39) v1(38.86,32.06) v1(38.84,30.4) v1(38.86,29) v1(38.86,28) v1(38.86,24.95) v1(38.86,23.94) v1(38.86,22.92) v1(39.76,37.55) v1(39.87,29) v1(39.87,28) v1(39.87,24.95) v1(39.87,23.94) v1(39.87,22.92) v1(40.24,45.28) v1(40.21,32.1) v1(40.24,30.45) v1(40.25,18.67) v1(40.25,9.39) v1(40.5,16.71) v1(40.63,12.21) v1(40.98,54.01) v1(40.98,9.56) v1(41.91,24.95) v1(42.08,18.69) v1(42.25,52.74) v1(43.52,52.74) v1(44.3,41.51) v1(44.89,38.86) v1(45.01,39.61) v1(45.27,37.84) v1(45.33,35.98) v1(46.57,21.97) v1(46.8,30.83) v1(46.91,39.33) v1(46.93,36.26) v1(48.36,36.36) v1(48.6,9.56) v1(48.95,11.67) v1(49.51,19.61) v1(49.87,36.23) v1(49.87,26.07) v1(49.87,24.8) v1(49.87,14.64) v1(49.87,3.21) v1(50.1,18.21) v1(51.14,47.66) v1(51.7,9.3) v1(52.31,41.64) v1(52.41,51.47) v1(52.41,48.93) v1(52.41,43.85) v1(53.26,32.99) v1(53.54,34.62) v1(53.68,50.2) v1(53.68,15.91) v1(53.68,13.37) v1(53.7,1.59) v1(53.8,6.33) v1(54.88,6.33) v1(54.95,48.93) v1(54.95,42.58) v1(56.07,34.88) v1(56.22,42.58) v1(56.31,36.05) v1(56.91,34.93) v1(57.44,17.75) v1(57.71,37.28) v1(57.9,9.66) v1(58.19,43.27) v1(58.19,42.07) v1(58.19,40.62) v1(58.38,17.75) v1(58.76,7.02) v1(58.76,1.94) v1(58.94,35.31) v1(59.57,2.65) v1(60.03,51.47) v1(60.03,42.58) v1(60.03,13.37) v1(60.41,9.11) v1(62.35,3.58) v1(62.57,43.85) v1(62.57,42.58) v1(62.57,15.91) v1(62.57,13.37) v1(62.57,7.02) v1(62.74,0.98) v1(63.02,36.68) v1(63.84,51.47) v1(63.84,48.93) v1(63.84,43.85) v1(63.84,42.58) v1(63.84,40.04) v1(63.84,10.83) v1(63.84,9.56) v1(63.84,7.02) v1(64.02,3.96) v1(64.18,31.72) v1(64.23,33.29) v1(64.75,0.98) v1(65.11,46.39) v1(65.11,43.85) v1(65.11,42.58) v1(65.11,40.04) v1(65.11,18.45) v1(65.11,14.64) v1(65.11,10.83) v1(65.11,9.56) v1(65.54,26.65) v1(65.87,32.1) v1(65.91,28.97) v1(66.15,23.89) v1(66.24,27.11) v1(66.38,50.2) v1(66.38,43.85) v1(66.38,42.58) v1(66.38,10.83) v1(66.38,1.94) v1(66.41,29.48) v1(66.53,21.95) v1(66.74,25.32) v1(66.92,29.99) v1(66.92,28.97) v1(67.02,27.03) v1(67.15,22.91) v1(67.43,29.48) v1(67.6,26.48) v1(67.65,42.58) v1(67.76,22.37) v1(67.89,31.68) v1(67.94,29.99) v1(67.94,27.03) v1(68.05,14.83) v1(68.19,25.88) v1(68.45,29.48) v1(68.45,26.52) v1(68.59,22.4) v1(68.95,29.99) v1(68.95,28.97) v1(68.95,27.03) v1(68.95,26.01) v1(68.92,4.48) v1(69.39,22.38) v1(69.46,29.48) v1(69.46,26.52) v1(69.76,31.36) v1(69.97,29.99) v1(69.97,28.97) v1(69.97,27.03) v1(69.97,26.01) v1(69.97,25) v1(69.97,23.98) v1(70.09,32.6) v1(70.02,23.13) v1(70.19,52.74) v1(70.19,51.47) v1(70.19,50.2) v1(70.19,37.5) v1(70.19,36.23) v1(70.19,34.96) v1(70.19,5.75) v1(70.19,3.21) v1(70.19,1.94) v1(70.27,22.37) v1(70.35,20.28) v1(70.48,29.48) v1(70.48,26.52) v1(70.87,9.59) v1(70.99,29.99) v1(70.99,27.03) v1(70.99,26.01) v1(70.99,24.99) v1(70.99,23.98) v1(70.99,23.2) v1(71.07,22.32) v1(71.22,50) v1(71.22,6.01) v1(71.31,54.43) v1(71.31,53.41) v1(71.31,52.4) v1(71.31,51.38) v1(71.31,4.62) v1(71.31,3.61) v1(71.31,2.59) v1(71.31,1.57) v1(71.46,46.39) v1(71.46,42.58) v1(71.46,37.5) v1(71.46,36.23) v1(71.49,29.48) v1(71.49,26.52) v1(71.44,14.4) v1(71.52,30.77) v1(71.53,12.62) v1(71.73,50.5) v1(71.73,49.49) v1(71.73,6.51) v1(71.73,5.5) v1(71.81,54.94) v1(71.81,53.92) v1(71.81,52.9) v1(71.81,51.89) v1(71.81,4.11) v1(71.81,3.1) v1(71.81,2.08) v1(71.81,1.07) v1(72,29.99) v1(72,26.01) v1(72,24.99) v1(72,23.98) v1(72,23.22) v1(71.98,16.96) v1(72.24,50) v1(72.24,6.01) v1(72.32,54.43) v1(72.32,53.41) v1(72.32,52.4) v1(72.32,51.38) v1(72.32,4.62) v1(72.32,3.61) v1(72.32,2.59) v1(72.32,1.57) v1(72.51,29.48) v1(72.51,26.52) v1(72.74,49.49) v1(72.73,47.66) v1(72.73,46.39) v1(72.73,45.12) v1(72.73,43.85) v1(72.73,42.58) v1(72.73,41.31) v1(72.73,40.04) v1(72.73,38.77) v1(72.73,37.5) v1(72.73,36.23) v1(72.73,34.96) v1(72.73,12.1) v1(72.74,6.51) v1(73.02,29.99) v1(73.02,28.97) v1(73.02,27.03) v1(73.02,26.01) v1(73.02,24.99) v1(73.02,23.98) v1(73.02,22.96) v1(73.09,21.62) v1(73.02,19.99) v1(73.25,50) v1(73.25,6.01) v1(73.53,29.48) v1(73.53,26.52) v1(73.76,49.49) v1(73.72,7.42) v1(73.76,6.51) v1(74,48.93) v1(74,47.66) v1(74,46.39) v1(74,45.12) v1(74,43.85) v1(74,42.58) v1(74,41.31) v1(74,40.04) v1(74,38.77) v1(74,37.5) v1(74,36.23) v1(74,34.96) v1(74,33.69) v1(74.03,29.99) v1(74.03,23.98) v1(74.27,50) v1(74.27,6.01) v1(74.56,28.99) v1(74.56,27.01) v1(74.78,49.49) v1(74.78,48.47) v1(74.78,47.46) v1(74.78,46.44) v1(74.78,45.42) v1(74.78,44.41) v1(74.78,43.39) v1(74.78,42.38) v1(74.78,41.36) v1(74.78,40.34) v1(74.78,39.33) v1(74.78,38.31) v1(74.78,37.3) v1(74.78,36.28) v1(74.78,35.26) v1(74.78,34.25) v1(74.78,33.23) v1(74.78,32.22) v1(74.78,22.77) v1(74.78,21.75) v1(74.78,20.74) v1(74.78,19.72) v1(74.78,18.7) v1(74.78,17.69) v1(74.78,16.67) v1(74.78,15.66) v1(74.78,14.64) v1(74.78,13.62) v1(74.78,12.61) v1(74.78,11.59) v1(74.78,10.58) v1(74.78,9.56) v1(74.78,8.54) v1(74.78,7.53) v1(74.78,6.51) v1(75.28,50) v1(75.28,48.98) v1(75.28,47.96) v1(75.28,46.95) v1(75.28,45.93) v1(75.28,44.92) v1(75.28,43.9) v1(75.28,42.88) v1(75.28,41.87) v1(75.28,40.85) v1(75.28,39.84) v1(75.28,38.82) v1(75.28,37.8) v1(75.28,36.79) v1(75.28,35.77) v1(75.28,34.76) v1(75.28,33.74) v1(75.28,32.72) v1(75.28,31.71) v1(75.28,23.28) v1(75.28,22.26) v1(75.28,21.24) v1(75.28,20.23) v1(75.28,19.21) v1(75.28,18.2) v1(75.28,17.18) v1(75.28,16.16) v1(75.28,15.15) v1(75.28,14.13) v1(75.28,13.12) v1(75.28,12.1) v1(75.28,11.08) v1(75.28,10.07) v1(75.28,9.05) v1(75.28,8.04) v1(75.28,7.02) v1(75.28,6) v1(75.79,49.49) v1(75.79,48.47) v1(75.79,47.46) v1(75.79,46.44) v1(75.79,45.42) v1(75.79,44.41) v1(75.79,43.39) v1(75.79,42.38) v1(75.79,41.36) v1(75.79,40.34) v1(75.79,39.33) v1(75.79,38.31) v1(75.79,37.3) v1(75.79,36.28) v1(75.79,35.26) v1(75.79,34.25) v1(75.79,33.23) v1(75.79,32.22) v1(75.79,31.2) v1(75.79,30.18) v1(75.79,25.82) v1(75.79,24.8) v1(75.79,23.78) v1(75.79,22.77) v1(75.79,21.75) v1(75.79,20.74) v1(75.79,19.72) v1(75.79,18.7) v1(75.79,17.69) v1(75.79,16.67) v1(75.79,15.66) v1(75.79,14.64) v1(75.79,13.62) v1(75.79,12.61) v1(75.79,11.59) v1(75.79,10.58) v1(75.79,9.56) v1(75.79,8.54) v1(75.79,7.53) v1(75.79,6.51) v1(77.74,49.49) v1(77.74,48.47) v1(77.74,47.46) v1(77.74,46.44) v1(77.74,45.42) v1(77.74,44.41) v1(77.74,43.39) v1(77.74,42.38) v1(77.74,41.36) v1(77.74,40.34) v1(77.74,39.33) v1(77.74,38.31) v1(77.74,37.3) v1(77.74,36.28) v1(77.74,35.26) v1(77.74,34.25) v1(77.74,33.23) v1(77.74,32.22) v1(77.74,31.2) v1(77.75,30.31) v1(77.75,25.69) v1(77.74,24.8) v1(77.74,23.78) v1(77.74,22.77) v1(77.74,21.75) v1(77.74,20.74) v1(77.74,19.72) v1(77.74,18.7) v1(77.74,17.69) v1(77.74,16.67) v1(77.74,15.66) v1(77.74,14.64) v1(77.74,13.62) v1(77.74,12.61) v1(77.74,11.59) v1(77.74,10.58) v1(77.74,9.56) v1(77.74,8.54) v1(77.74,7.53) v1(77.74,6.51) v1(78.25,50) v1(78.25,48.98) v1(78.25,47.96) v1(78.25,46.95) v1(78.25,45.93) v1(78.25,44.92) v1(78.25,43.9) v1(78.25,42.88) v1(78.25,41.87) v1(78.25,40.85) v1(78.25,39.84) v1(78.25,38.82) v1(78.25,37.8) v1(78.25,36.79) v1(78.25,35.77) v1(78.25,34.76) v1(78.25,33.74) v1(78.25,32.72) v1(78.25,23.28) v1(78.25,22.26) v1(78.25,21.24) v1(78.25,20.23) v1(78.25,19.21) v1(78.25,18.2) v1(78.25,17.18) v1(78.25,16.16) v1(78.25,15.15) v1(78.25,14.13) v1(78.25,13.12) v1(78.25,12.1) v1(78.25,11.08) v1(78.25,10.07) v1(78.25,9.05) v1(78.25,8.04) v1(78.25,7.02) v1(78.25,6) v1(78.45,28.5) v1(78.45,27.5) v1(78.54,31.49) v1(78.52,30.68) v1(78.52,25.32) v1(78.54,24.51) v1(78.76,49.49) v1(78.76,48.47) v1(78.76,47.46) v1(78.76,46.44) v1(78.76,45.42) v1(78.76,44.41) v1(78.76,43.39) v1(78.76,42.38) v1(78.76,41.36) v1(78.76,40.34) v1(78.76,39.33) v1(78.76,38.31) v1(78.76,37.3) v1(78.76,36.28) v1(78.76,35.26) v1(78.76,34.25) v1(78.76,33.23) v1(78.76,32.22) v1(78.76,23.78) v1(78.76,22.77) v1(78.76,21.75) v1(78.76,20.74) v1(78.76,19.72) v1(78.76,18.7) v1(78.76,17.69) v1(78.76,16.67) v1(78.76,15.66) v1(78.76,14.64) v1(78.76,13.62) v1(78.76,12.61) v1(78.76,11.59) v1(78.76,10.58) v1(78.76,9.56) v1(78.76,8.54) v1(78.76,7.53) v1(78.76,6.51) v1(79.06,28) v1(79.27,50) v1(79.23,32.72) v1(79.28,28.88) v1(79.28,27.12) v1(79.23,23.28) v1(79.27,6.01) v1(79.34,31.09) v1(79.34,24.91) v1(79.65,32) v1(79.65,24) v1(79.77,49.49) v1(79.78,28.38) v1(79.78,27.62) v1(79.77,6.51) v1(79.96,32.91) v1(79.96,23.09) v1(80.1,29.29) v1(80.1,26.71) v1(80.16,31.49) v1(80.16,24.51) v1(80.28,50) v1(80.28,6.01) v1(80.47,32.41) v1(80.42,28) v1(80.47,23.59) v1(80.6,28.79) v1(80.6,27.21) v1(80.79,49.49) v1(80.78,33.32) v1(80.78,22.68) v1(80.79,6.51) v1(80.98,31.9) v1(80.92,29.69) v1(80.92,26.31) v1(80.98,24.1) v1(81.09,28.3) v1(81.09,27.7) v1(81.21,54.43) v1(81.21,53.41) v1(81.21,52.4) v1(81.21,51.38) v1(81.3,50) v1(81.29,32.81) v1(81.29,23.19) v1(81.3,6.01) v1(81.21,4.62) v1(81.21,3.61) v1(81.21,2.59) v1(81.21,1.57) v1(81.42,29.19) v1(81.42,26.81) v1(81.6,33.72) v1(81.6,22.28) v1(81.72,54.94) v1(81.72,53.92) v1(81.72,52.9) v1(81.72,51.89) v1(81.8,32.3) v1(81.74,30.1) v1(81.78,28) v1(81.74,25.9) v1(81.8,23.7) v1(81.72,4.11) v1(81.72,3.1) v1(81.72,2.08) v1(81.72,1.07) v1(81.81,50.5) v1(81.81,49.49) v1(81.81,6.51) v1(81.81,5.5) v1(81.91,28.7) v1(81.91,27.3) v1(82.11,33.22) v1(82.11,22.78) v1(82.23,54.43) v1(82.23,53.41) v1(82.23,52.4) v1(82.23,51.38) v1(82.23,29.6) v1(82.23,26.4) v1(82.23,4.62) v1(82.23,3.61) v1(82.23,2.59) v1(82.23,1.57) v1(82.31,50) v1(82.31,6.01) v1(82.42,34.13) v1(82.42,21.87) v1(82.56,30.5) v1(82.56,25.5) v1(82.62,32.71) v1(82.62,23.29) v1(82.74,54.94) v1(82.74,53.92) v1(82.74,52.9) v1(82.74,51.89) v1(82.73,29.1) v1(82.73,26.9) v1(82.74,4.11) v1(82.74,3.1) v1(82.74,2.08) v1(82.74,1.07) v1(82.82,50.5) v1(82.82,49.49) v1(82.82,6.51) v1(82.82,5.5) v1(82.93,33.62) v1(82.93,22.38) v1(83.05,30) v1(83.05,26) v1(83.24,54.43) v1(83.24,53.41) v1(83.24,52.4) v1(83.24,51.38) v1(83.25,34.52) v1(83.25,21.48) v1(83.24,4.62) v1(83.24,3.6) v1(83.24,2.59) v1(83.24,1.57) v1(83.38,30.91) v1(83.38,25.09) v1(83.48,50) v1(83.44,33.11) v1(83.44,22.89) v1(83.48,6) v1(83.55,29.51) v1(83.55,26.49) v1(83.75,53.92) v1(83.75,52.9) v1(83.75,51.89) v1(83.75,50.87) v1(83.76,34.01) v1(83.76,21.99) v1(83.75,5.13) v1(83.75,4.11) v1(83.75,3.1) v1(83.75,2.08) v1(83.87,30.41) v1(83.87,25.59) v1(84.08,34.91) v1(84.08,21.09) v1(84.2,31.31) v1(84.2,24.69) v1(84.26,53.41) v1(84.26,52.4) v1(84.26,51.38) v1(84.26,50.36) v1(84.27,33.51) v1(84.27,22.49) v1(84.26,5.64) v1(84.26,4.62) v1(84.26,3.6) v1(84.26,2.59) v1(84.37,29.91) v1(84.37,26.09) v1(84.59,34.4) v1(84.59,21.6) v1(84.69,30.81) v1(84.69,25.19) v1(84.77,52.9) v1(84.77,51.89) v1(84.77,50.87) v1(84.77,5.13) v1(84.77,4.11) v1(84.77,3.1) v1(84.91,35.28) v1(84.91,20.72) v1(85.09,33.89) v1(85.02,31.71) v1(85.02,24.29) v1(85.09,22.11) v1(85.19,30.32) v1(85.19,25.68) v1(85.28,52.4) v1(85.28,51.38) v1(85.28,50.36) v1(85.28,5.64) v1(85.28,4.62) v1(85.28,3.6) v1(85.42,34.77) v1(85.42,21.23) v1(85.52,31.21) v1(85.52,24.79) v1(85.78,51.89) v1(85.78,50.87) v1(85.78,49.86) v1(85.73,35.69) v1(85.73,20.31) v1(85.78,6.14) v1(85.78,5.13) v1(85.78,4.11) v1(85.85,32.09) v1(85.85,23.91) v1(85.93,34.27) v1(85.93,21.73) v1(86.02,30.71) v1(86.02,25.29) v1(86.29,51.38) v1(86.29,50.36) v1(86.29,49.35) v1(86.24,35.18) v1(86.24,20.82) v1(86.29,6.65) v1(86.29,5.64) v1(86.29,4.62) v1(86.37,36.19) v1(86.35,31.6) v1(86.35,24.4) v1(86.37,19.81) v1(86.68,32.47) v1(86.68,23.53) v1(86.8,50.87) v1(86.8,49.86) v1(86.8,48.84) v1(86.75,34.67) v1(86.75,21.33) v1(86.8,7.16) v1(86.8,6.14) v1(86.8,5.13) v1(86.81,35.52) v1(86.85,31.1) v1(86.85,24.9) v1(86.81,20.48) v1(86.97,36.61) v1(86.97,19.39) v1(87.19,31.96) v1(87.19,24.04) v1(87.31,50.36) v1(87.31,49.35) v1(87.31,48.33) v1(87.31,7.67) v1(87.31,6.65) v1(87.31,5.64) v1(87.42,35.93) v1(87.42,20.07) v1(87.51,37.13) v1(87.53,35.15) v1(87.51,32.86) v1(87.51,23.14) v1(87.53,20.85) v1(87.51,18.87) v1(87.7,31.45) v1(87.7,24.55) v1(87.82,49.86) v1(87.82,48.84) v1(87.82,47.82) v1(87.82,8.18) v1(87.82,7.16) v1(87.82,6.14) v1(87.99,36.42) v1(87.99,19.58) v1(88.08,37.71) v1(88.02,32.36) v1(88.02,23.64) v1(88.08,18.29) v1(88.26,35.7) v1(88.3,33.32) v1(88.3,22.68) v1(88.26,20.3) v1(88.32,49.35) v1(88.32,48.33) v1(88.32,47.32) v1(88.32,8.68) v1(88.32,7.67) v1(88.32,6.65) v1(88.53,36.99) v1(88.52,31.85) v1(88.52,24.15) v1(88.53,19.01) v1(88.64,38.44) v1(88.64,17.56) v1(88.83,48.84) v1(88.83,47.82) v1(88.83,46.81) v1(88.81,32.81) v1(88.81,23.19) v1(88.83,9.19) v1(88.83,8.18) v1(88.83,7.16) v1(88.94,36.31) v1(88.94,19.69) v1(89.09,37.71) v1(89.05,33.84) v1(89.05,22.16) v1(89.09,18.29) v1(89.2,39.16) v1(89.2,16.84) v1(89.34,48.33) v1(89.34,47.32) v1(89.34,46.3) v1(89.32,32.31) v1(89.32,23.69) v1(89.34,9.7) v1(89.34,8.68) v1(89.34,7.67) v1(89.55,36.99) v1(89.56,33.33) v1(89.56,22.67) v1(89.55,19.01) v1(89.65,38.44) v1(89.65,17.56) v1(89.76,39.88) v1(89.76,34.42) v1(89.76,21.58) v1(89.76,16.12) v1(89.85,47.82) v1(89.85,46.81) v1(89.85,45.79) v1(89.85,10.21) v1(89.85,9.19) v1(89.85,8.18) v1(90.07,32.83) v1(90.07,23.17) v1(90.11,37.71) v1(90.11,18.29) v1(90.21,39.16) v1(90.27,33.91) v1(90.27,22.09) v1(90.21,16.84) v1(90.36,47.32) v1(90.36,46.3) v1(90.36,45.28) v1(90.32,40.6) v1(90.32,15.4) v1(90.36,10.72) v1(90.36,9.7) v1(90.36,8.68) v1(90.43,35.05) v1(90.43,20.95) v1(90.67,38.44) v1(90.67,17.56) v1(90.77,39.88) v1(90.78,33.4) v1(90.78,22.6) v1(90.77,16.12) v1(90.86,46.81) v1(90.86,45.79) v1(90.86,44.78) v1(90.88,41.33) v1(90.88,14.67) v1(90.86,11.22) v1(90.86,10.21) v1(90.86,9.19) v1(90.93,34.54) v1(90.93,21.46) v1(91.12,35.65) v1(91.12,20.35) v1(91.23,39.16) v1(91.23,16.84) v1(91.37,46.3) v1(91.37,45.28) v1(91.37,44.27) v1(91.33,40.6) v1(91.33,15.4) v1(91.37,11.73) v1(91.37,10.72) v1(91.37,9.7) v1(91.44,42.05) v1(91.44,34.03) v1(91.44,21.97) v1(91.44,13.95) v1(91.63,35.14) v1(91.63,20.86) v1(91.79,39.88) v1(91.79,16.12) v1(91.88,45.79) v1(91.88,44.78) v1(91.88,43.76) v1(91.88,42.74) v1(91.9,41.33) v1(91.84,36.21) v1(91.84,19.79) v1(91.9,14.67) v1(91.88,13.26) v1(91.88,12.24) v1(91.88,11.22) v1(91.88,10.21) v1(92.13,34.63) v1(92.13,21.37) v1(92.39,45.28) v1(92.39,44.27) v1(92.39,43.25) v1(92.35,40.6) v1(92.35,35.7) v1(92.35,20.3) v1(92.35,15.4) v1(92.39,12.75) v1(92.39,11.73) v1(92.39,10.72) v1(92.46,42.05) v1(92.46,13.95) v1(92.56,36.77) v1(92.56,19.23) v1(92.9,44.78) v1(92.9,43.76) v1(92.9,42.74) v1(92.86,35.19) v1(92.86,20.81) v1(92.9,13.26) v1(92.9,12.24) v1(92.9,11.22) v1(92.91,41.33) v1(92.91,14.67) v1(93.07,36.26) v1(93.07,19.74) v1(93.28,37.33) v1(93.28,18.67) v1(93.4,44.27) v1(93.4,43.25) v1(93.47,42.05) v1(93.47,13.95) v1(93.4,12.75) v1(93.4,11.73) v1(93.58,35.75) v1(93.58,20.25) v1(93.79,36.82) v1(93.79,19.18) v1(93.91,43.76) v1(93.91,12.24) v1(94.01,42.74) v1(94.01,37.89) v1(94.01,18.11) v1(94.01,13.26) v1(94.3,36.31) v1(94.3,19.69) v1(94.42,43.25) v1(94.42,12.75) v1(94.52,37.38) v1(94.52,18.62) v1(94.73,38.45) v1(94.73,17.55) v1(95.02,36.87) v1(95.02,19.13) v1(95.24,37.94) v1(95.24,18.06) v1(95.45,39.01) v1(95.45,16.99) v1(95.75,37.43) v1(95.75,18.57) v1(95.96,38.5) v1(95.96,17.5) v1(96.17,39.57) v1(96.17,16.43) v1(96.47,37.99) v1(96.47,18.01) v1(96.68,39.06) v1(96.68,16.94) v1(96.96,39.75) v1(96.96,16.25) v1(97.19,38.55) v1(97.19,17.45) v1(97.24,40.39) v1(97.24,15.61) v1(97.5,39.16) v1(97.5,16.84) v1(97.78,37.87) v1(97.78,18.13) v1(97.87,39.81) v1(97.87,16.19) v1(98.15,38.51) v1(98.15,17.49) v1(98.43,37.22) v1(98.43,18.78) v1(98.52,39.16) v1(98.52,16.84) v1(98.8,37.87) v1(98.8,18.13) v1(99.07,36.57) v1(99.07,19.43) v1(99.16,38.51) v1(99.16,17.49) v1(99.44,37.22) v1(99.44,18.78) v1(99.72,35.93) v1(99.72,20.07) v1(99.81,37.87) v1(99.81,18.13) v1(100.09,36.57) v1(100.09,19.43) v1(100.37,35.28) v1(100.37,20.72) v1(100.46,37.22) v1(100.46,18.78) v1(100.74,35.93) v1(100.74,20.07) v1(101.01,34.63) v1(101.01,21.37) v1(101.1,36.57) v1(101.1,19.43) v1(101.38,35.28) v1(101.38,20.72) v1(101.66,33.99) v1(101.66,22.01) v1(101.75,35.93) v1(101.75,20.07) v1(102.03,34.63) v1(102.03,21.37) v1(102.4,35.28) v1(102.31,33.34) v1(102.31,22.66) v1(102.4,20.72) v1(102.67,33.99) v1(102.67,22.01) v1(102.95,32.69) v1(102.95,23.31) v1(103.04,34.63) v1(103.04,21.37) v1(103.32,33.34) v1(103.32,22.66) v1(103.6,32.05) v1(103.6,23.95) v1(103.69,33.99) v1(103.69,22.01) v1(103.97,32.69) v1(103.97,23.31) v1(104.25,31.4) v1(104.25,24.6) v1(104.34,33.34) v1(104.34,22.66) v1(104.61,32.05) v1(104.61,23.95) v1(104.89,30.75) v1(104.89,25.25) v1(104.98,32.69) v1(104.98,23.31) v1(105.26,31.4) v1(105.26,24.6) v1(105.54,30.11) v1(105.54,25.89) v1(105.63,32.05) v1(105.63,23.95) v1(105.91,30.75) v1(105.91,25.25) v1(106.18,29.46) v1(106.18,26.54) v1(106.28,31.4) v1(106.28,24.6) v1(106.55,30.11) v1(106.55,25.89) v1(106.83,28.81) v1(106.83,27.19) v1(106.92,30.75) v1(106.92,25.25) v1(107.2,29.46) v1(107.2,26.54) v1(107.23,28) v1(107.57,30.11) v1(107.57,25.89) v1(107.85,28.81) v1(107.85,27.19) v1(108.22,29.46) v1(108.25,28) v1(108.22,26.54) v1(108.86,28.81) v1(108.86,27.19) v1(109.26,28) v2(34.79,29) v2(34.79,28) v2(34.79,26.98) v2(35.81,29) v2(35.81,26.98) v2(36.83,29) v2(36.83,28) v2(36.83,26.98) v2(45.08,29.73) v2(45.08,28.71) v2(56.02,16.4) v2(56.02,15.77) v2(56.78,16.4) v2(56.78,15.77) v2(57.55,16.4) v2(58.12,27.76) v2(58.12,26.74) v2(58.12,25.75) v2(58.12,24.73) v2(58.12,23.72) v2(59.14,27.76) v2(59.14,26.74) v2(59.14,25.75) v2(59.14,24.73) v2(59.14,23.72) v2(59.37,17.65) v2(60.16,27.76) v2(60.16,26.74) v2(60.16,25.75) v2(60.16,24.73) v2(61.17,27.76) v2(61.17,26.74) v2(61.17,25.75) v2(61.17,24.73) v2(61.17,23.72) v2(62.2,27.76) v2(62.2,26.74) v2(62.2,24.73) v2(62.2,23.72) v2(63.93,29.16) v2(73.09,28.3) v2(73.09,27.7) v2(75.93,55.36) v2(75.93,54.36) v2(75.93,53.36) v2(75.93,52.31) v2(75.93,51.36) v2(75.93,4.64) v2(75.93,3.69) v2(75.93,2.64) v2(75.93,1.64) v2(75.93,0.64) v2(77.61,55.36) v2(77.61,54.36) v2(77.61,53.36) v2(77.61,52.31) v2(77.61,51.36) v2(77.61,4.64) v2(77.61,3.69) v2(77.61,2.64) v2(77.61,1.64) v2(77.61,0.64)
